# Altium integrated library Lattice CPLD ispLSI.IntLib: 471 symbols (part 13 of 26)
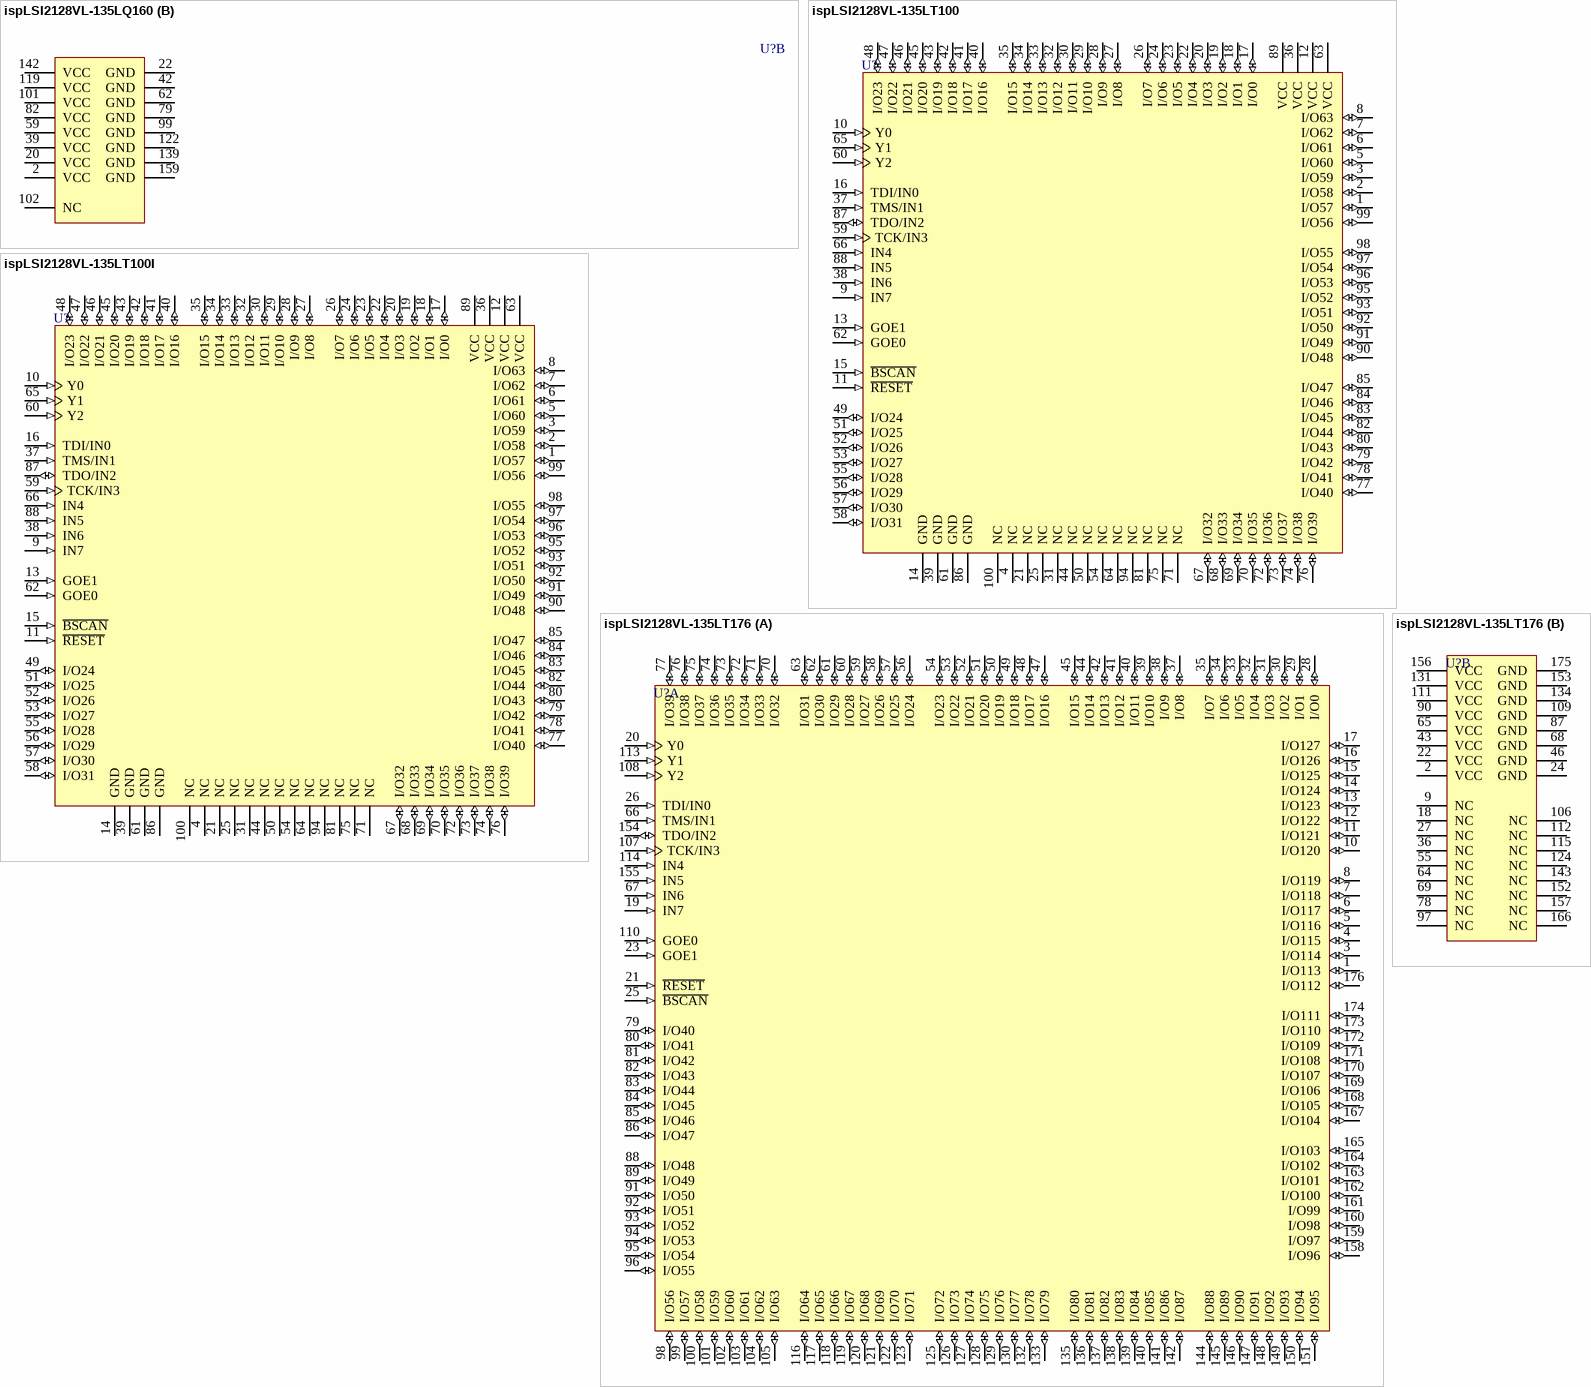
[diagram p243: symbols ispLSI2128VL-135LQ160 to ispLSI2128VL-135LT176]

## ispLSI2128VL-135LT176
designator U?
2.5V In-System Programmable SuperFAST High Density PLD
footprint TQFP176_N (Thin QFP, 176-Leads, Body 24x24mm, Pitch 0.5mm, IPC Medium Density)
footprint TQFP176_L (Thin QFP, 176-Leads, Body 24x24mm, Pitch 0.5mm, IPC High Density)
footprint TQFP176_M (Thin QFP, 176-Leads, Body 24x24mm, Pitch 0.5mm, IPC Low Density)
3D model 2128VL-TQFP176 (176-Pin Thin Quad Flat Pack 0.5 mm Pitch)
part A pins: 1 I/O113 (io), 3 I/O114 (io), 4 I/O115 (io), 5 I/O116 (io), 6 I/O117 (io), 7 I/O118 (io), 8 I/O119 (io), 10 I/O120 (io), 11 I/O121 (io), 12 I/O122 (io), 13 I/O123 (io), 14 I/O124 (io), 15 I/O125 (io), 16 I/O126 (io), 17 I/O127 (io), 19 IN7 (in), 20 Y0 (in), 21 ~{RESET} (in), 23 GOE1 (in), 25 ~{BSCAN} (in), 26 TDI/IN0 (in), 28 I/O0 (io), 29 I/O1 (io), 30 I/O2 (io), 31 I/O3 (io), 32 I/O4 (io), 33 I/O5 (io), 34 I/O6 (io), 35 I/O7 (io), 37 I/O8 (io), 38 I/O9 (io), 39 I/O10 (io), 40 I/O11 (io), 41 I/O12 (io), 42 I/O13 (io), 44 I/O14 (io), 45 I/O15 (io), 47 I/O16 (io), 48 I/O17 (io), 49 I/O18 (io), 50 I/O19 (io), 51 I/O20 (io), 52 I/O21 (io), 53 I/O22 (io), 54 I/O23 (io), 56 I/O24 (io), 57 I/O25 (io), 58 I/O26 (io), 59 I/O27 (io), 60 I/O28 (io), 61 I/O29 (io), 62 I/O30 (io), 63 I/O31 (io), 66 TMS/IN1 (in), 67 IN6 (in), 70 I/O32 (io), 71 I/O33 (io), 72 I/O34 (io), 73 I/O35 (io), 74 I/O36 (io), 75 I/O37 (io), 76 I/O38 (io), 77 I/O39 (io), 79 I/O40 (io), 80 I/O41 (io), 81 I/O42 (io), 82 I/O43 (io), 83 I/O44 (io), 84 I/O45 (io), 85 I/O46 (io), 86 I/O47 (io), 88 I/O48 (io), 89 I/O49 (io), 91 I/O50 (io), 92 I/O51 (io), 93 I/O52 (io), 94 I/O53 (io), 95 I/O54 (io), 96 I/O55 (io), 98 I/O56 (io), 99 I/O57 (io), 100 I/O58 (io), 101 I/O59 (io), 102 I/O60 (io), 103 I/O61 (io), 104 I/O62 (io), 105 I/O63 (io), 107 TCK/IN3 (in), 108 Y2 (in), 110 GOE0 (in), 113 Y1 (in), 114 IN4 (in), 116 I/O64 (io), 117 I/O65 (io), 118 I/O66 (io), 119 I/O67 (io), 120 I/O68 (io), 121 I/O69 (io), 122 I/O70 (io), 123 I/O71 (io), 125 I/O72 (io), 126 I/O73 (io), 127 I/O74 (io), 128 I/O75 (io), 129 I/O76 (io), 130 I/O77 (io), 132 I/O78 (io), 133 I/O79 (io), 135 I/O80 (io), 136 I/O81 (io), 137 I/O82 (io), 138 I/O83 (io), 139 I/O84 (io), 140 I/O85 (io), 141 I/O86 (io), 142 I/O87 (io), 144 I/O88 (io), 145 I/O89 (io), 146 I/O90 (io), 147 I/O91 (io), 148 I/O92 (io), 149 I/O93 (io), 150 I/O94 (io), 151 I/O95 (io), 154 TDO/IN2 (io), 155 IN5 (in), 158 I/O96 (io), 159 I/O97 (io), 160 I/O98 (io), 161 I/O99 (io), 162 I/O100 (io), 163 I/O101 (io), 164 I/O102 (io), 165 I/O103 (io), 167 I/O104 (io), 168 I/O105 (io), 169 I/O106 (io), 170 I/O107 (io), 171 I/O108 (io), 172 I/O109 (io), 173 I/O110 (io), 174 I/O111 (io), 176 I/O112 (io)
part B pins: 2 VCC (power), 9 NC, 18 NC, 22 VCC (power), 24 GND (power), 27 NC, 36 NC, 43 VCC (power), 46 GND (power), 55 NC, 64 NC, 65 VCC (power), 68 GND (power), 69 NC, 78 NC, 87 GND (power), 90 VCC (power), 97 NC, 106 NC, 109 GND (power), 111 VCC (power), 112 NC, 115 NC, 124 NC, 131 VCC (power), 134 GND (power), 143 NC, 152 NC, 153 GND (power), 156 VCC (power), 157 NC, 166 NC, 175 GND (power)

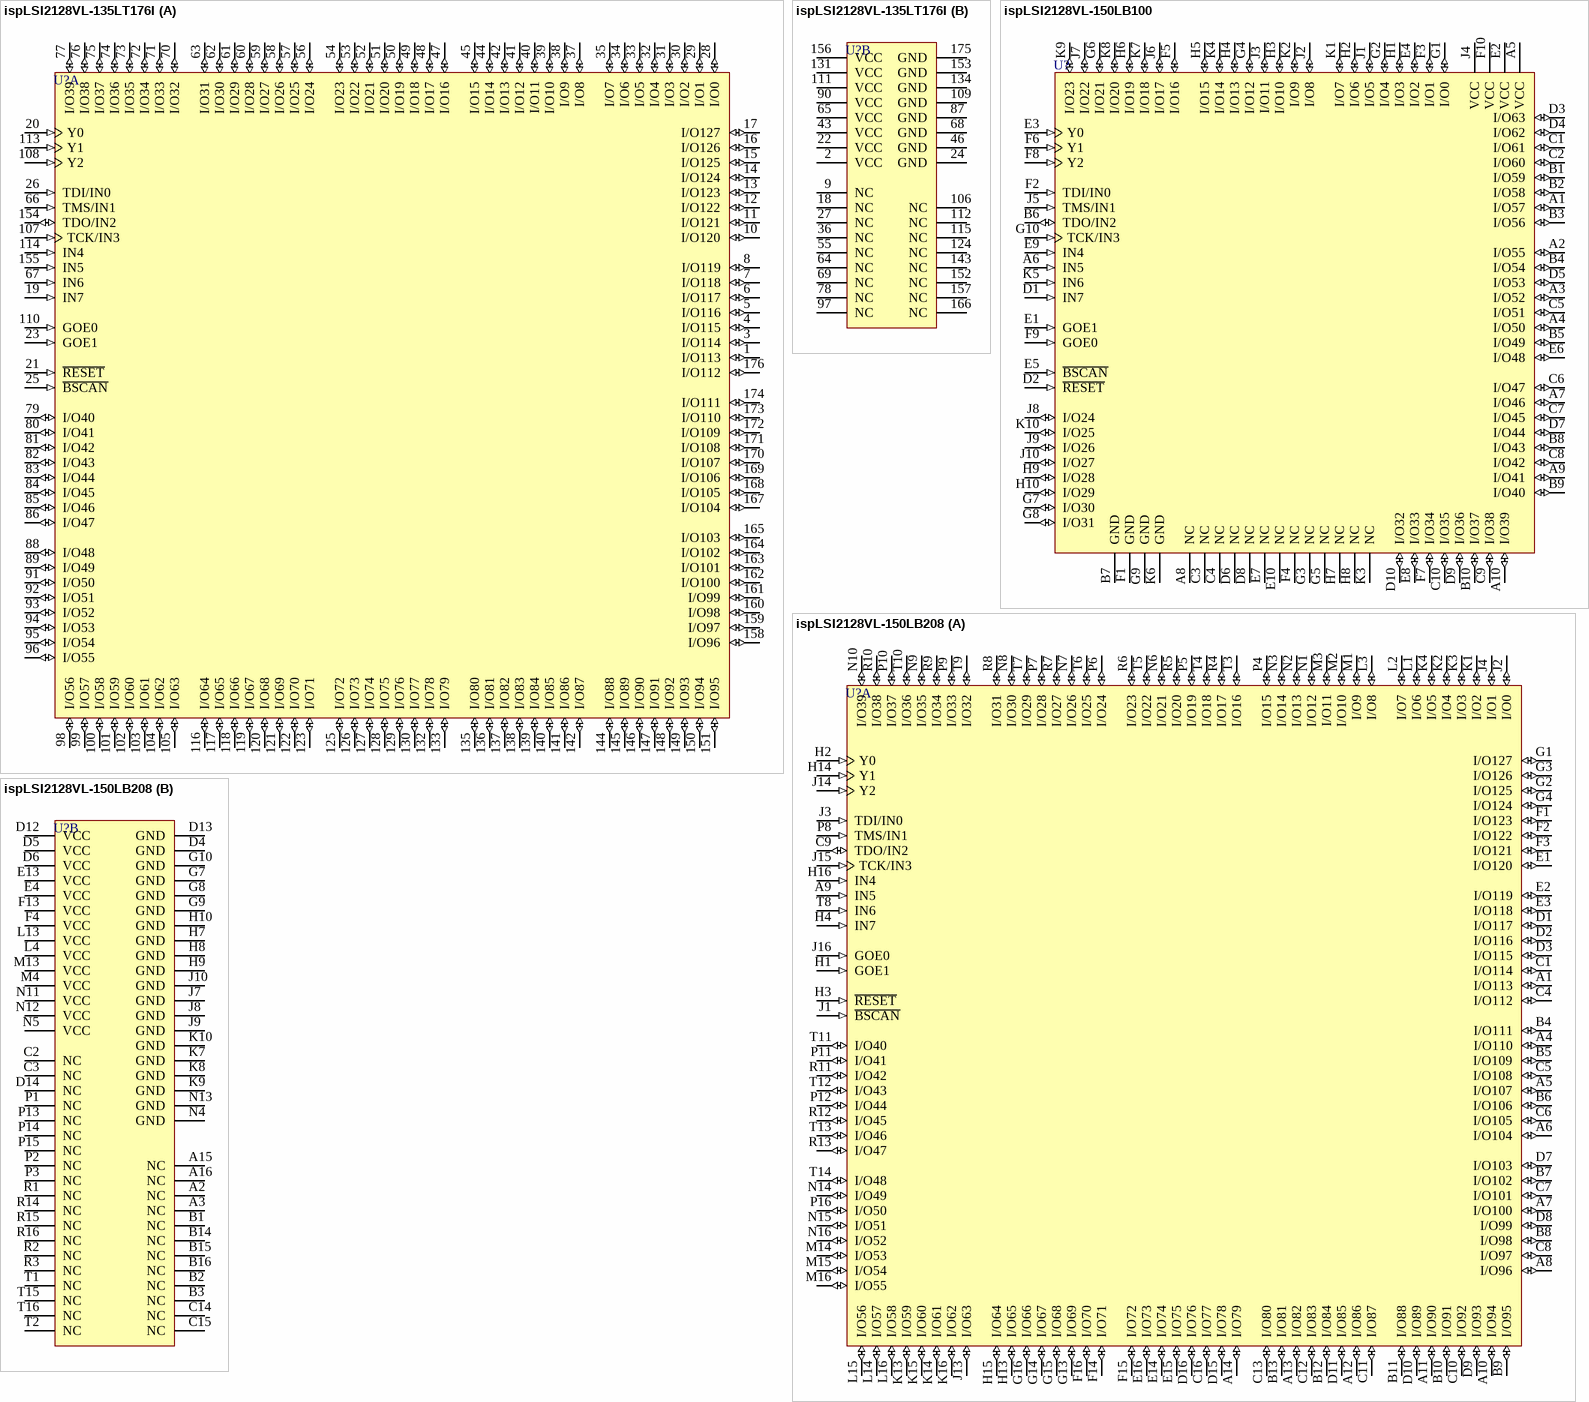
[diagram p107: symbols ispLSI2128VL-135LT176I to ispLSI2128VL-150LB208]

## ispLSI2128VL-135LT176I
designator U?
2.5V In-System Programmable SuperFAST High Density PLD
footprint TQFP176_N (Thin QFP, 176-Leads, Body 24x24mm, Pitch 0.5mm, IPC Medium Density)
footprint TQFP176_L (Thin QFP, 176-Leads, Body 24x24mm, Pitch 0.5mm, IPC High Density)
footprint TQFP176_M (Thin QFP, 176-Leads, Body 24x24mm, Pitch 0.5mm, IPC Low Density)
3D model 2128VL-TQFP176 (176-Pin Thin Quad Flat Pack 0.5 mm Pitch)
part A pins: 1 I/O113 (io), 3 I/O114 (io), 4 I/O115 (io), 5 I/O116 (io), 6 I/O117 (io), 7 I/O118 (io), 8 I/O119 (io), 10 I/O120 (io), 11 I/O121 (io), 12 I/O122 (io), 13 I/O123 (io), 14 I/O124 (io), 15 I/O125 (io), 16 I/O126 (io), 17 I/O127 (io), 19 IN7 (in), 20 Y0 (in), 21 ~{RESET} (in), 23 GOE1 (in), 25 ~{BSCAN} (in), 26 TDI/IN0 (in), 28 I/O0 (io), 29 I/O1 (io), 30 I/O2 (io), 31 I/O3 (io), 32 I/O4 (io), 33 I/O5 (io), 34 I/O6 (io), 35 I/O7 (io), 37 I/O8 (io), 38 I/O9 (io), 39 I/O10 (io), 40 I/O11 (io), 41 I/O12 (io), 42 I/O13 (io), 44 I/O14 (io), 45 I/O15 (io), 47 I/O16 (io), 48 I/O17 (io), 49 I/O18 (io), 50 I/O19 (io), 51 I/O20 (io), 52 I/O21 (io), 53 I/O22 (io), 54 I/O23 (io), 56 I/O24 (io), 57 I/O25 (io), 58 I/O26 (io), 59 I/O27 (io), 60 I/O28 (io), 61 I/O29 (io), 62 I/O30 (io), 63 I/O31 (io), 66 TMS/IN1 (in), 67 IN6 (in), 70 I/O32 (io), 71 I/O33 (io), 72 I/O34 (io), 73 I/O35 (io), 74 I/O36 (io), 75 I/O37 (io), 76 I/O38 (io), 77 I/O39 (io), 79 I/O40 (io), 80 I/O41 (io), 81 I/O42 (io), 82 I/O43 (io), 83 I/O44 (io), 84 I/O45 (io), 85 I/O46 (io), 86 I/O47 (io), 88 I/O48 (io), 89 I/O49 (io), 91 I/O50 (io), 92 I/O51 (io), 93 I/O52 (io), 94 I/O53 (io), 95 I/O54 (io), 96 I/O55 (io), 98 I/O56 (io), 99 I/O57 (io), 100 I/O58 (io), 101 I/O59 (io), 102 I/O60 (io), 103 I/O61 (io), 104 I/O62 (io), 105 I/O63 (io), 107 TCK/IN3 (in), 108 Y2 (in), 110 GOE0 (in), 113 Y1 (in), 114 IN4 (in), 116 I/O64 (io), 117 I/O65 (io), 118 I/O66 (io), 119 I/O67 (io), 120 I/O68 (io), 121 I/O69 (io), 122 I/O70 (io), 123 I/O71 (io), 125 I/O72 (io), 126 I/O73 (io), 127 I/O74 (io), 128 I/O75 (io), 129 I/O76 (io), 130 I/O77 (io), 132 I/O78 (io), 133 I/O79 (io), 135 I/O80 (io), 136 I/O81 (io), 137 I/O82 (io), 138 I/O83 (io), 139 I/O84 (io), 140 I/O85 (io), 141 I/O86 (io), 142 I/O87 (io), 144 I/O88 (io), 145 I/O89 (io), 146 I/O90 (io), 147 I/O91 (io), 148 I/O92 (io), 149 I/O93 (io), 150 I/O94 (io), 151 I/O95 (io), 154 TDO/IN2 (io), 155 IN5 (in), 158 I/O96 (io), 159 I/O97 (io), 160 I/O98 (io), 161 I/O99 (io), 162 I/O100 (io), 163 I/O101 (io), 164 I/O102 (io), 165 I/O103 (io), 167 I/O104 (io), 168 I/O105 (io), 169 I/O106 (io), 170 I/O107 (io), 171 I/O108 (io), 172 I/O109 (io), 173 I/O110 (io), 174 I/O111 (io), 176 I/O112 (io)
part B pins: 2 VCC (power), 9 NC, 18 NC, 22 VCC (power), 24 GND (power), 27 NC, 36 NC, 43 VCC (power), 46 GND (power), 55 NC, 64 NC, 65 VCC (power), 68 GND (power), 69 NC, 78 NC, 87 GND (power), 90 VCC (power), 97 NC, 106 NC, 109 GND (power), 111 VCC (power), 112 NC, 115 NC, 124 NC, 131 VCC (power), 134 GND (power), 143 NC, 152 NC, 153 GND (power), 156 VCC (power), 157 NC, 166 NC, 175 GND (power)

## ispLSI2128VL-150LB100
designator U?
2.5V In-System Programmable SuperFAST High Density PLD
footprint caBGA100 (BGA, 100-Leads, Body 10x10mm, Pitch 0.8mm)
3D model 2128VL-caBGA100 (100-Ball Chip Array Ball Grid Array (caBGA100))
pins: A1 I/O57 (io), A2 I/O55 (io), A3 I/O52 (io), A4 I/O50 (io), A5 VCC (power), A6 IN5 (in), A7 I/O46 (io), A8 NC, A9 I/O41 (io), A10 I/O39 (io), B1 I/O59 (io), B2 I/O58 (io), B3 I/O56 (io), B4 I/O54 (io), B5 I/O49 (io), B6 TDO/IN2 (io), B7 GND (power), B8 I/O43 (io), B9 I/O40 (io), B10 I/O37 (io), C1 I/O61 (io), C2 I/O60 (io), C3 NC, C4 NC, C5 I/O51 (io), C6 I/O47 (io), C7 I/O45 (io), C8 I/O42 (io), C9 I/O38 (io), C10 I/O35 (io), D1 IN7 (in), D2 ~{RESET} (in), D3 I/O63 (io), D4 I/O62 (io), D5 I/O53 (io), D6 NC, D7 I/O44 (io), D8 NC, D9 I/O36 (io), D10 I/O32 (io), E1 GOE1 (in), E2 VCC (power), E3 Y0 (in), E4 I/O2 (io), E5 ~{BSCAN} (in), E6 I/O48 (io), E7 NC, E8 I/O33 (io), E9 IN4 (in), E10 NC, F1 GND (power), F2 TDI/IN0 (in), F3 I/O1 (io), F4 NC, F5 I/O16 (io), F6 Y1 (in), F7 I/O34 (io), F8 Y2 (in), F9 GOE0 (in), F10 VCC (power), G1 I/O0 (io), G2 I/O4 (io), G3 NC, G4 I/O12 (io), G5 NC, G6 I/O21 (io), G7 I/O30 (io), G8 I/O31 (io), G9 GND (power), G10 TCK/IN3 (in), H1 I/O3 (io), H2 I/O6 (io), H3 I/O10 (io), H4 I/O13 (io), H5 I/O15 (io), H6 I/O19 (io), H7 NC, H8 NC, H9 I/O28 (io), H10 I/O29 (io), J1 I/O5 (io), J2 I/O8 (io), J3 I/O11 (io), J4 VCC (power), J5 TMS/IN1 (in), J6 I/O17 (io), J7 I/O22 (io), J8 I/O24 (io), J9 I/O26 (io), J10 I/O27 (io), K1 I/O7 (io), K2 I/O9 (io), K3 NC, K4 I/O14 (io), K5 IN6 (in), K6 GND (power), K7 I/O18 (io), K8 I/O20 (io), K9 I/O23 (io), K10 I/O25 (io)

## ispLSI2128VL-150LB208
designator U?
2.5V In-System Programmable SuperFAST High Density PLD
footprint fpBGA208 (BGA, 208-Leads, Body 17x17mm, Pitch 1mm)
3D model 2128VL-fpBGA208 (208-Ball Fine Pitch Ball Grid Array (fpBGA208))
part A pins: A1 I/O113 (io), A4 I/O110 (io), A5 I/O107 (io), A6 I/O104 (io), A7 I/O100 (io), A8 I/O96 (io), A9 IN5 (in), A10 I/O94 (io), A11 I/O90 (io), A12 I/O86 (io), A13 I/O82 (io), A14 I/O79 (io), B4 I/O111 (io), B5 I/O109 (io), B6 I/O106 (io), B7 I/O102 (io), B8 I/O98 (io), B9 I/O95 (io), B10 I/O91 (io), B11 I/O88 (io), B12 I/O84 (io), B13 I/O81 (io), C1 I/O114 (io), C4 I/O112 (io), C5 I/O108 (io), C6 I/O105 (io), C7 I/O101 (io), C8 I/O97 (io), C9 TDO/IN2 (io), C10 I/O92 (io), C11 I/O87 (io), C12 I/O83 (io), C13 I/O80 (io), C16 I/O77 (io), D1 I/O117 (io), D2 I/O116 (io), D3 I/O115 (io), D7 I/O103 (io), D8 I/O99 (io), D9 I/O93 (io), D10 I/O89 (io), D11 I/O85 (io), D15 I/O78 (io), D16 I/O76 (io), E1 I/O120 (io), E2 I/O119 (io), E3 I/O118 (io), E14 I/O74 (io), E15 I/O75 (io), E16 I/O73 (io), F1 I/O123 (io), F2 I/O122 (io), F3 I/O121 (io), F14 I/O71 (io), F15 I/O72 (io), F16 I/O70 (io), G1 I/O127 (io), G2 I/O125 (io), G3 I/O126 (io), G4 I/O124 (io), G13 I/O69 (io), G14 I/O67 (io), G15 I/O68 (io), G16 I/O66 (io), H1 GOE1 (in), H2 Y0 (in), H3 ~{RESET} (in), H4 IN7 (in), H13 I/O65 (io), H14 Y1 (in), H15 I/O64 (io), H16 IN4 (in), J1 ~{BSCAN} (in), J2 I/O0 (io), J3 TDI/IN0 (in), J4 I/O1 (io), J13 I/O63 (io), J14 Y2 (in), J15 TCK/IN3 (in), J16 GOE0 (in), K1 I/O2 (io), K2 I/O4 (io), K3 I/O3 (io), K4 I/O5 (io), K13 I/O59 (io), K14 I/O61 (io), K15 I/O60 (io), K16 I/O62 (io), L1 I/O6 (io), L2 I/O7 (io), L3 I/O8 (io), L14 I/O57 (io), L15 I/O56 (io), L16 I/O58 (io), M1 I/O9 (io), M2 I/O10 (io), M3 I/O11 (io), M14 I/O53 (io), M15 I/O54 (io), M16 I/O55 (io), N1 I/O12 (io), N2 I/O13 (io), N3 I/O14 (io), N6 I/O21 (io), N7 I/O26 (io), N8 I/O30 (io), N9 I/O35 (io), N10 I/O39 (io), N14 I/O49 (io), N15 I/O51 (io), N16 I/O52 (io), P4 I/O15 (io), P5 I/O19 (io), P6 I/O24 (io), P7 I/O28 (io), P8 TMS/IN1 (in), P9 I/O33 (io), P10 I/O37 (io), P11 I/O41 (io), P12 I/O44 (io), P16 I/O50 (io), R4 I/O17 (io), R5 I/O20 (io), R6 I/O23 (io), R7 I/O27 (io), R8 I/O31 (io), R9 I/O34 (io), R10 I/O38 (io), R11 I/O42 (io), R12 I/O45 (io), R13 I/O47 (io), T3 I/O16 (io), T4 I/O18 (io), T5 I/O22 (io), T6 I/O25 (io), T7 I/O29 (io), T8 IN6 (in), T9 I/O32 (io), T10 I/O36 (io), T11 I/O40 (io), T12 I/O43 (io), T13 I/O46 (io), T14 I/O48 (io)
part B pins: A2 NC, A3 NC, A15 NC, A16 NC, B1 NC, B2 NC, B3 NC, B14 NC, B15 NC, B16 NC, C2 NC, C3 NC, C14 NC, C15 NC, D4 GND (power), D5 VCC (power), D6 VCC (power), D12 VCC (power), D13 GND (power), D14 NC, E4 VCC (power), E13 VCC (power), F4 VCC (power), F13 VCC (power), G7 GND (power), G8 GND (power), G9 GND (power), G10 GND (power), H7 GND (power), H8 GND (power), H9 GND (power), H10 GND (power), J7 GND (power), J8 GND (power), J9 GND (power), J10 GND (power), K7 GND (power), K8 GND (power), K9 GND (power), K10 GND (power), L4 VCC (power), L13 VCC (power), M4 VCC (power), M13 VCC (power), N4 GND (power), N5 VCC (power), N11 VCC (power), N12 VCC (power), N13 GND (power), P1 NC, P2 NC, P3 NC, P13 NC, P14 NC, P15 NC, R1 NC, R2 NC, R3 NC, R14 NC, R15 NC, R16 NC, T1 NC, T2 NC, T15 NC, T16 NC

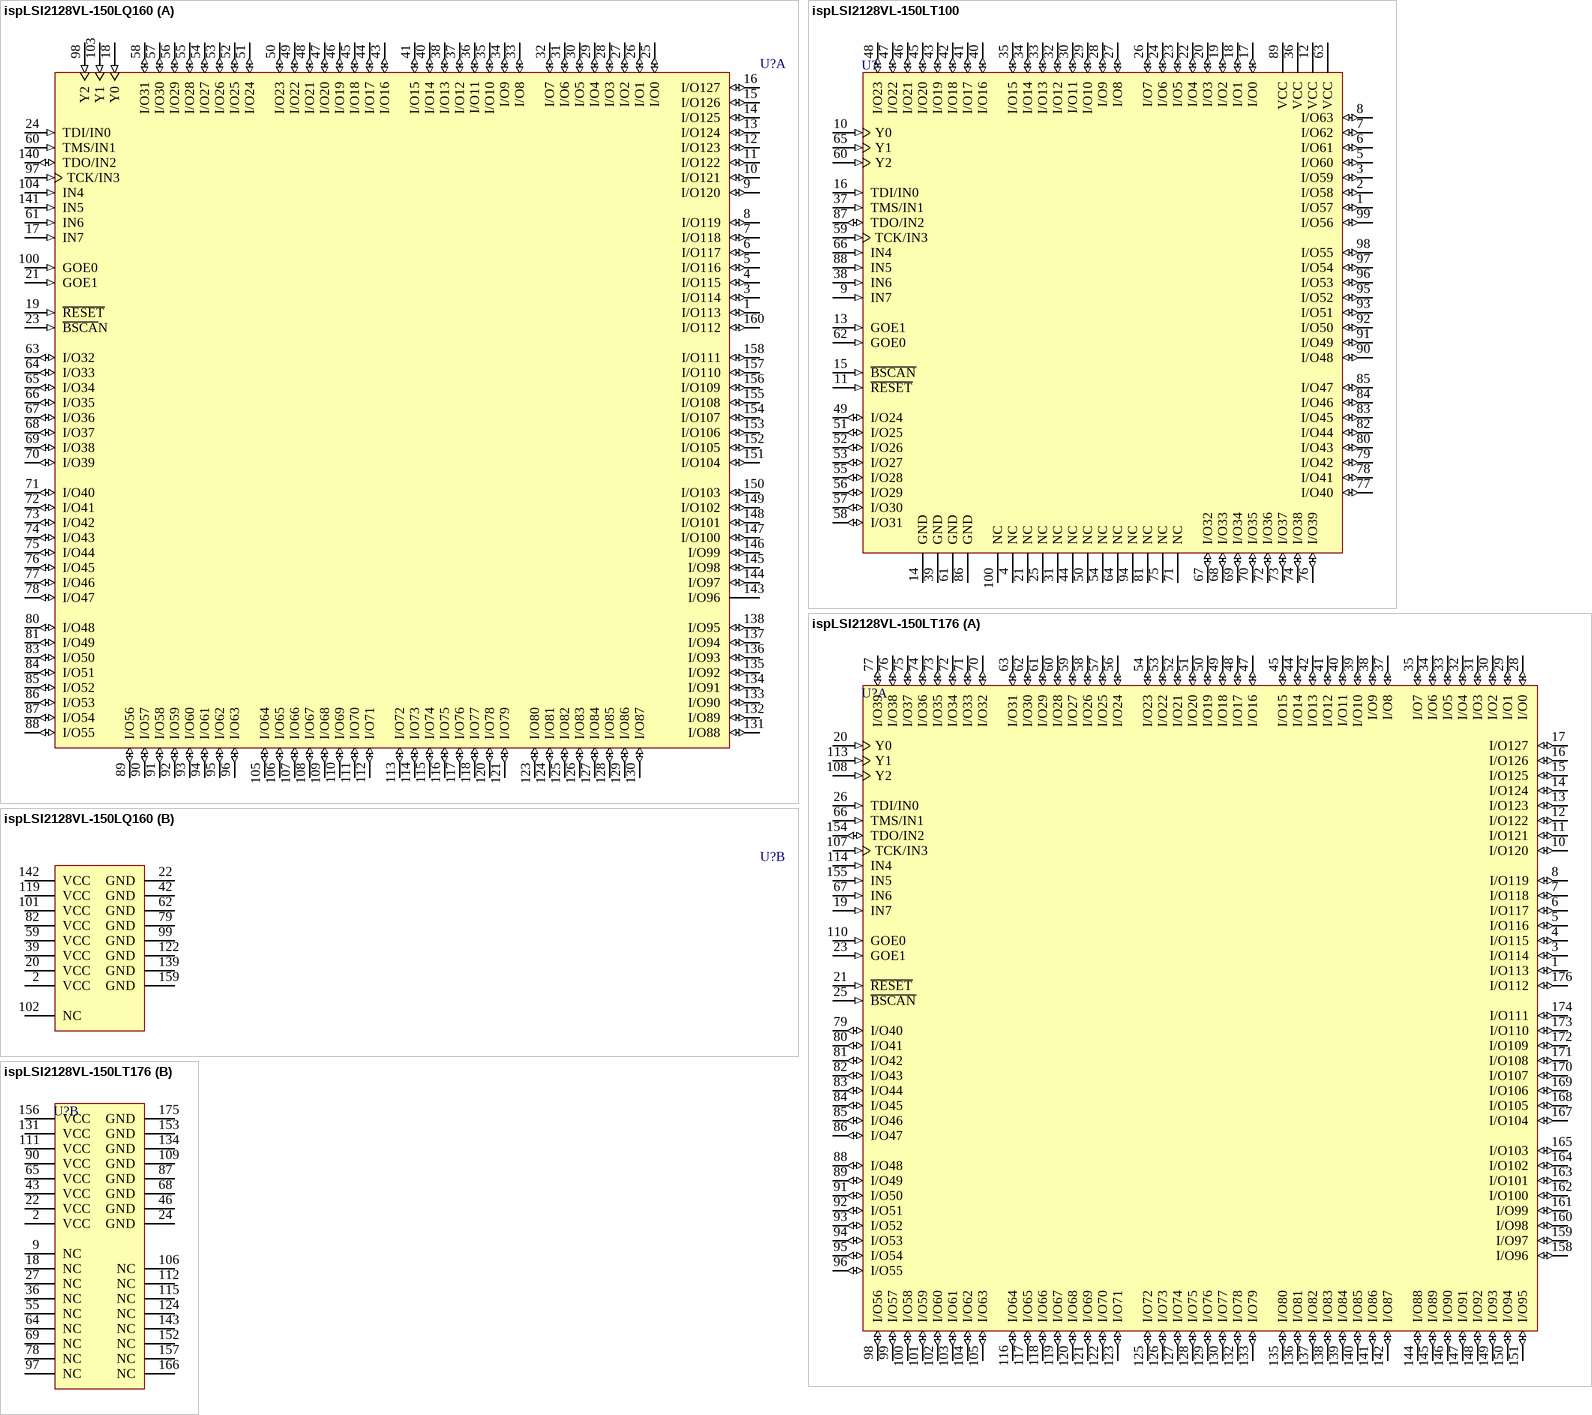
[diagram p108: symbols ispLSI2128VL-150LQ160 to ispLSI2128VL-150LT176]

## ispLSI2128VL-150LQ160
designator U?
2.5V In-System Programmable SuperFAST High Density PLD
footprint PQFP160_N (QFP, 160-Leads, Body 28 x 28mm, Pitch 0.65mm, IPC Medium Density)
footprint PQFP160_L (QFP, 160-Leads, Body 28 x 28mm, Pitch 0.65mm, IPC High Density)
footprint PQFP160_M (QFP, 160-Leads, Body 28 x 28mm, Pitch 0.65mm, IPC Low Density)
3D model 2128VL-PQFP160 (160-Pin Quad Flat Pack 0.65 mm Pitch)
part A pins: 1 I/O113 (io), 3 I/O114 (io), 4 I/O115 (io), 5 I/O116 (io), 6 I/O117 (io), 7 I/O118 (io), 8 I/O119 (io), 9 I/O120 (io), 10 I/O121 (io), 11 I/O122 (io), 12 I/O123 (io), 13 I/O124 (io), 14 I/O125 (io), 15 I/O126 (io), 16 I/O127 (io), 17 IN7 (in), 18 Y0 (in), 19 ~{RESET} (in), 21 GOE1 (in), 23 ~{BSCA}N (in), 24 TDI/IN0 (in), 25 I/O0 (io), 26 I/O1 (io), 27 I/O2 (io), 28 I/O3 (io), 29 I/O4 (io), 30 I/O5 (io), 31 I/O6 (io), 32 I/O7 (io), 33 I/O8 (io), 34 I/O9 (io), 35 I/O10 (io), 36 I/O11 (io), 37 I/O12 (io), 38 I/O13 (io), 40 I/O14 (io), 41 I/O15 (io), 43 I/O16 (io), 44 I/O17 (io), 45 I/O18 (io), 46 I/O19 (io), 47 I/O20 (io), 48 I/O21 (io), 49 I/O22 (io), 50 I/O23 (io), 51 I/O24 (io), 52 I/O25 (io), 53 I/O26 (io), 54 I/O27 (io), 55 I/O28 (io), 56 I/O29 (io), 57 I/O30 (io), 58 I/O31 (io), 60 TMS/IN1 (in), 61 IN6 (in), 63 I/O32 (io), 64 I/O33 (io), 65 I/O34 (io), 66 I/O35 (io), 67 I/O36 (io), 68 I/O37 (io), 69 I/O38 (io), 70 I/O39 (io), 71 I/O40 (io), 72 I/O41 (io), 73 I/O42 (io), 74 I/O43 (io), 75 I/O44 (io), 76 I/O45 (io), 77 I/O46 (io), 78 I/O47 (io), 80 I/O48 (io), 81 I/O49 (io), 83 I/O50 (io), 84 I/O51 (io), 85 I/O52 (io), 86 I/O53 (io), 87 I/O54 (io), 88 I/O55 (io), 89 I/O56 (io), 90 I/O57 (io), 91 I/O58 (io), 92 I/O59 (io), 93 I/O60 (io), 94 I/O61 (io), 95 I/O62 (io), 96 I/O63 (io), 97 TCK/IN3 (in), 98 Y2 (in), 100 GOE0 (in), 103 Y1 (in), 104 IN4 (in), 105 I/O64 (io), 106 I/O65 (io), 107 I/O66 (io), 108 I/O67 (io), 109 I/O68 (io), 110 I/O69 (io), 111 I/O70 (io), 112 I/O71 (io), 113 I/O72 (io), 114 I/O73 (io), 115 I/O74 (io), 116 I/O75 (io), 117 I/O76 (io), 118 I/O77 (io), 120 I/O78 (io), 121 I/O79 (io), 123 I/O80 (io), 124 I/O81 (io), 125 I/O82 (io), 126 I/O83 (io), 127 I/O84 (io), 128 I/O85 (io), 129 I/O86 (io), 130 I/O87 (io), 131 I/O88 (io), 132 I/O89 (io), 133 I/O90 (io), 134 I/O91 (io), 135 I/O92 (io), 136 I/O93 (io), 137 I/O94 (io), 138 I/O95 (io), 140 TDO/IN2 (io), 141 IN5 (in), 143 I/O96 (power), 144 I/O97 (io), 145 I/O98 (io), 146 I/O99 (io), 147 I/O100 (io), 148 I/O101 (io), 149 I/O102 (io), 150 I/O103 (io), 151 I/O104 (io), 152 I/O105 (io), 153 I/O106 (io), 154 I/O107 (io), 155 I/O108 (io), 156 I/O109 (io), 157 I/O110 (io), 158 I/O111 (io), 160 I/O112 (io)
part B pins: 2 VCC (power), 20 VCC (power), 22 GND (power), 39 VCC (power), 42 GND (power), 59 VCC (power), 62 GND (power), 79 GND (power), 82 VCC (power), 99 GND (power), 101 VCC (power), 102 NC, 119 VCC (power), 122 GND (power), 139 GND (power), 142 VCC (power), 159 GND (power)

## ispLSI2128VL-150LT100
designator U?
2.5V In-System Programmable SuperFAST High Density PLD
footprint TQFP100_N (Thin QFP, 100-Leads, Body 14x14mm, Pitch 0.5mm, IPC Medium Density)
footprint TQFP100_L (Thin QFP, 100-Leads, Body 14x14mm, Pitch 0.5mm, IPC High Density)
footprint TQFP100_M (Thin QFP, 100-Leads, Body 14x14mm, Pitch 0.5mm, IPC Low Density)
3D model 2128VL-TQFP100 (100-Pin Thin Quad Flat Pack (TQFP100))
pins: 1 I/O57 (io), 2 I/O58 (io), 3 I/O59 (io), 4 NC, 5 I/O60 (io), 6 I/O61 (io), 7 I/O62 (io), 8 I/O63 (io), 9 IN7 (in), 10 Y0 (in), 11 ~{RESET} (in), 12 VCC (power), 13 GOE1 (in), 14 GND (power), 15 ~{BSCAN} (in), 16 TDI/IN0 (in), 17 I/O0 (io), 18 I/O1 (io), 19 I/O2 (io), 20 I/O3 (io), 21 NC, 22 I/O4 (io), 23 I/O5 (io), 24 I/O6 (io), 25 NC, 26 I/O7 (io), 27 I/O8 (io), 28 I/O9 (io), 29 I/O10 (io), 30 I/O11 (io), 31 NC, 32 I/O12 (io), 33 I/O13 (io), 34 I/O14 (io), 35 I/O15 (io), 36 VCC (power), 37 TMS/IN1 (in), 38 IN6 (in), 39 GND (power), 40 I/O16 (io), 41 I/O17 (io), 42 I/O18 (io), 43 I/O19 (io), 44 NC, 45 I/O20 (io), 46 I/O21 (io), 47 I/O22 (io), 48 I/O23 (io), 49 I/O24 (io), 50 NC, 51 I/O25 (io), 52 I/O26 (io), 53 I/O27 (io), 54 NC, 55 I/O28 (io), 56 I/O29 (io), 57 I/O30 (io), 58 I/O31 (io), 59 TCK/IN3 (in), 60 Y2 (in), 61 GND (power), 62 GOE0 (in), 63 VCC (power), 64 NC, 65 Y1 (in), 66 IN4 (in), 67 I/O32 (io), 68 I/O33 (io), 69 I/O34 (io), 70 I/O35 (io), 71 NC, 72 I/O36 (io), 73 I/O37 (io), 74 I/O38 (io), 75 NC, 76 I/O39 (io), 77 I/O40 (io), 78 I/O41 (io), 79 I/O42 (io), 80 I/O43 (io), 81 NC, 82 I/O44 (io), 83 I/O45 (io), 84 I/O46 (io), 85 I/O47 (io), 86 GND (power), 87 TDO/IN2 (io), 88 IN5 (in), 89 VCC (power), 90 I/O48 (io), 91 I/O49 (io), 92 I/O50 (io), 93 I/O51 (io), 94 NC, 95 I/O52 (io), 96 I/O53 (io), 97 I/O54 (io), 98 I/O55 (io), 99 I/O56 (io), 100 NC

## ispLSI2128VL-150LT176
designator U?
2.5V In-System Programmable SuperFAST High Density PLD
footprint TQFP176_N (Thin QFP, 176-Leads, Body 24x24mm, Pitch 0.5mm, IPC Medium Density)
footprint TQFP176_L (Thin QFP, 176-Leads, Body 24x24mm, Pitch 0.5mm, IPC High Density)
footprint TQFP176_M (Thin QFP, 176-Leads, Body 24x24mm, Pitch 0.5mm, IPC Low Density)
3D model 2128VL-TQFP176 (176-Pin Thin Quad Flat Pack 0.5 mm Pitch)
part A pins: 1 I/O113 (io), 3 I/O114 (io), 4 I/O115 (io), 5 I/O116 (io), 6 I/O117 (io), 7 I/O118 (io), 8 I/O119 (io), 10 I/O120 (io), 11 I/O121 (io), 12 I/O122 (io), 13 I/O123 (io), 14 I/O124 (io), 15 I/O125 (io), 16 I/O126 (io), 17 I/O127 (io), 19 IN7 (in), 20 Y0 (in), 21 ~{RESET} (in), 23 GOE1 (in), 25 ~{BSCAN} (in), 26 TDI/IN0 (in), 28 I/O0 (io), 29 I/O1 (io), 30 I/O2 (io), 31 I/O3 (io), 32 I/O4 (io), 33 I/O5 (io), 34 I/O6 (io), 35 I/O7 (io), 37 I/O8 (io), 38 I/O9 (io), 39 I/O10 (io), 40 I/O11 (io), 41 I/O12 (io), 42 I/O13 (io), 44 I/O14 (io), 45 I/O15 (io), 47 I/O16 (io), 48 I/O17 (io), 49 I/O18 (io), 50 I/O19 (io), 51 I/O20 (io), 52 I/O21 (io), 53 I/O22 (io), 54 I/O23 (io), 56 I/O24 (io), 57 I/O25 (io), 58 I/O26 (io), 59 I/O27 (io), 60 I/O28 (io), 61 I/O29 (io), 62 I/O30 (io), 63 I/O31 (io), 66 TMS/IN1 (in), 67 IN6 (in), 70 I/O32 (io), 71 I/O33 (io), 72 I/O34 (io), 73 I/O35 (io), 74 I/O36 (io), 75 I/O37 (io), 76 I/O38 (io), 77 I/O39 (io), 79 I/O40 (io), 80 I/O41 (io), 81 I/O42 (io), 82 I/O43 (io), 83 I/O44 (io), 84 I/O45 (io), 85 I/O46 (io), 86 I/O47 (io), 88 I/O48 (io), 89 I/O49 (io), 91 I/O50 (io), 92 I/O51 (io), 93 I/O52 (io), 94 I/O53 (io), 95 I/O54 (io), 96 I/O55 (io), 98 I/O56 (io), 99 I/O57 (io), 100 I/O58 (io), 101 I/O59 (io), 102 I/O60 (io), 103 I/O61 (io), 104 I/O62 (io), 105 I/O63 (io), 107 TCK/IN3 (in), 108 Y2 (in), 110 GOE0 (in), 113 Y1 (in), 114 IN4 (in), 116 I/O64 (io), 117 I/O65 (io), 118 I/O66 (io), 119 I/O67 (io), 120 I/O68 (io), 121 I/O69 (io), 122 I/O70 (io), 123 I/O71 (io), 125 I/O72 (io), 126 I/O73 (io), 127 I/O74 (io), 128 I/O75 (io), 129 I/O76 (io), 130 I/O77 (io), 132 I/O78 (io), 133 I/O79 (io), 135 I/O80 (io), 136 I/O81 (io), 137 I/O82 (io), 138 I/O83 (io), 139 I/O84 (io), 140 I/O85 (io), 141 I/O86 (io), 142 I/O87 (io), 144 I/O88 (io), 145 I/O89 (io), 146 I/O90 (io), 147 I/O91 (io), 148 I/O92 (io), 149 I/O93 (io), 150 I/O94 (io), 151 I/O95 (io), 154 TDO/IN2 (io), 155 IN5 (in), 158 I/O96 (io), 159 I/O97 (io), 160 I/O98 (io), 161 I/O99 (io), 162 I/O100 (io), 163 I/O101 (io), 164 I/O102 (io), 165 I/O103 (io), 167 I/O104 (io), 168 I/O105 (io), 169 I/O106 (io), 170 I/O107 (io), 171 I/O108 (io), 172 I/O109 (io), 173 I/O110 (io), 174 I/O111 (io), 176 I/O112 (io)
part B pins: 2 VCC (power), 9 NC, 18 NC, 22 VCC (power), 24 GND (power), 27 NC, 36 NC, 43 VCC (power), 46 GND (power), 55 NC, 64 NC, 65 VCC (power), 68 GND (power), 69 NC, 78 NC, 87 GND (power), 90 VCC (power), 97 NC, 106 NC, 109 GND (power), 111 VCC (power), 112 NC, 115 NC, 124 NC, 131 VCC (power), 134 GND (power), 143 NC, 152 NC, 153 GND (power), 156 VCC (power), 157 NC, 166 NC, 175 GND (power)

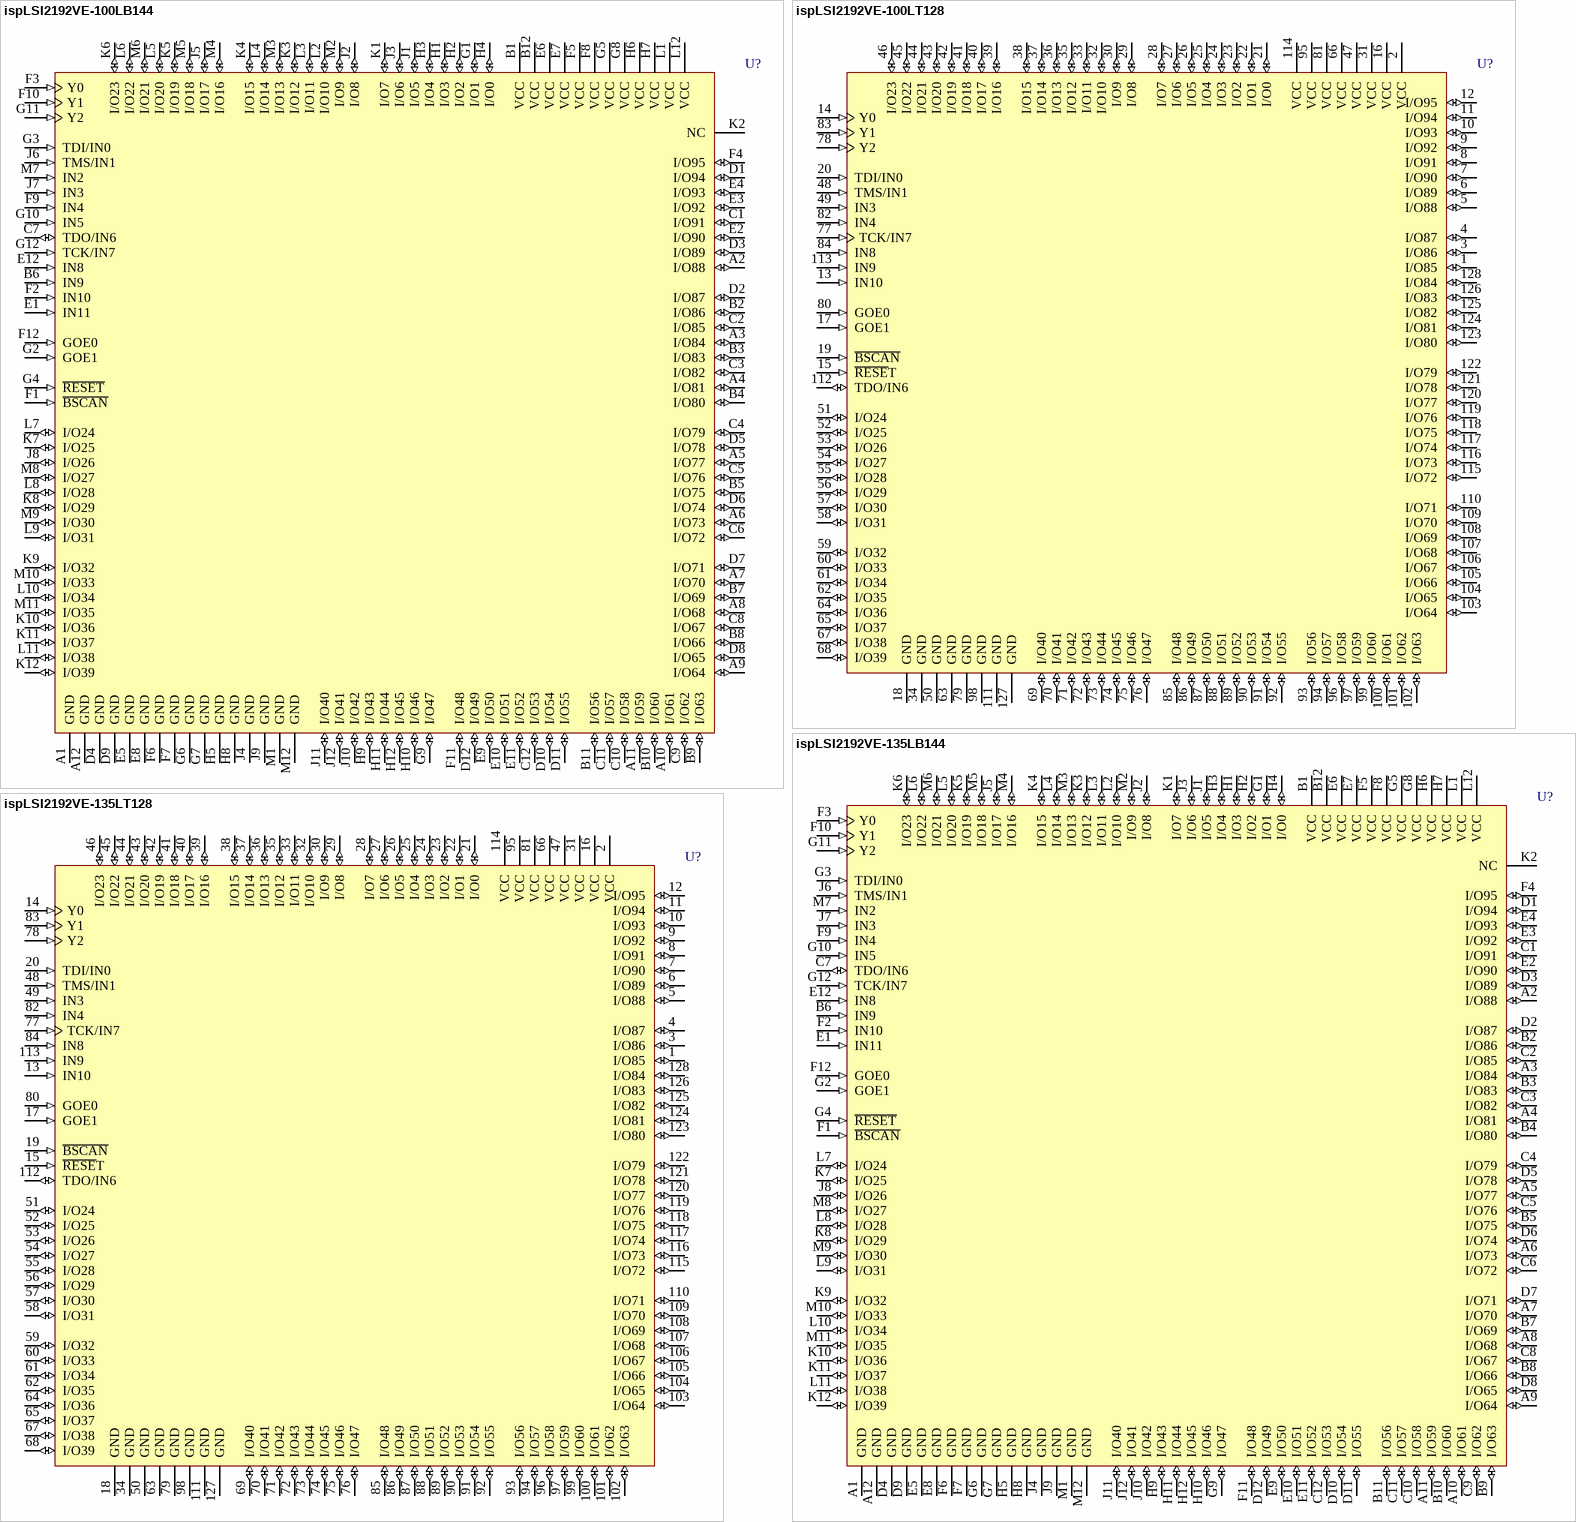
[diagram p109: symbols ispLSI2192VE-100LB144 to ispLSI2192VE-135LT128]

## ispLSI2192VE-100LB144
designator U?
3.3V In-System Programmable SuperFAST High Density PLD
footprint fpBGA144 (BGA, 144-Leads, Body 13x13mm, Pitch 1mm)
3D model 2192VE-fpBGA144 (144-Ball Fine Pitch Ball Grid Array (fpBGA144))
pins: A1 GND (power), A2 I/O88 (io), A3 I/O84 (io), A4 I/O81 (io), A5 I/O77 (io), A6 I/O73 (io), A7 I/O70 (io), A8 I/O68 (io), A9 I/O64 (io), A10 I/O61 (io), A11 I/O59 (io), A12 GND (power), B1 VCC (power), B2 I/O86 (io), B3 I/O83 (io), B4 I/O80 (io), B5 I/O75 (io), B6 IN9 (in), B7 I/O69 (io), B8 I/O66 (io), B9 I/O63 (io), B10 I/O60 (io), B11 I/O56 (io), B12 VCC (power), C1 I/O91 (io), C2 I/O85 (io), C3 I/O82 (io), C4 I/O79 (io), C5 I/O76 (io), C6 I/O72 (io), C7 TDO/IN6 (io), C8 I/O67 (io), C9 I/O62 (io), C10 I/O58 (io), C11 I/O57 (io), C12 I/O53 (io), D1 I/O94 (io), D2 I/O87 (io), D3 I/O89 (io), D4 GND (power), D5 I/O78 (io), D6 I/O74 (io), D7 I/O71 (io), D8 I/O65 (io), D9 GND (power), D10 I/O54 (io), D11 I/O55 (io), D12 I/O49 (io), E1 IN11 (in), E2 I/O90 (io), E3 I/O92 (io), E4 I/O93 (io), E5 GND (power), E6 VCC (power), E7 VCC (power), E8 GND (power), E9 I/O50 (io), E10 I/O51 (io), E11 I/O52 (io), E12 IN8 (in), F1 ~{BSCAN} (in), F2 IN10 (in), F3 Y0 (in), F4 I/O95 (io), F5 VCC (power), F6 GND (power), F7 GND (power), F8 VCC (power), F9 IN4 (in), F10 Y1 (in), F11 I/O48 (io), F12 GOE0 (in), G1 I/O1 (io), G2 GOE1 (in), G3 TDI/IN0 (in), G4 ~{RESET} (in), G5 VCC (power), G6 GND (power), G7 GND (power), G8 VCC (power), G9 I/O47 (io), G10 IN5 (in), G11 Y2 (in), G12 TCK/IN7 (in), H1 I/O3 (io), H2 I/O2 (io), H3 I/O4 (io), H4 I/O0 (io), H5 GND (power), H6 VCC (power), H7 VCC (power), H8 GND (power), H9 I/O43 (io), H10 I/O46 (io), H11 I/O44 (io), H12 I/O45 (io), J1 I/O5 (io), J2 I/O8 (io), J3 I/O6 (io), J4 GND (power), J5 I/O17 (io), J6 TMS/IN1 (in), J7 IN3 (in), J8 I/O26 (io), J9 GND (power), J10 I/O42 (io), J11 I/O40 (io), J12 I/O41 (io), K1 I/O7 (io), K2 NC, K3 I/O12 (io), K4 I/O15 (io), K5 I/O19 (io), K6 I/O23 (io), K7 I/O25 (io), K8 I/O29 (io), K9 I/O32 (io), K10 I/O36 (io), K11 I/O37 (io), K12 I/O39 (io), L1 VCC (power), L2 I/O10 (io), L3 I/O11 (io), L4 I/O14 (io), L5 I/O20 (io), L6 I/O22 (io), L7 I/O24 (io), L8 I/O28 (io), L9 I/O31 (io), L10 I/O34 (io), L11 I/O38 (io), L12 VCC (power), M1 GND (power), M2 I/O9 (io), M3 I/O13 (io), M4 I/O16 (io), M5 I/O18 (io), M6 I/O21 (io), M7 IN2 (in), M8 I/O27 (io), M9 I/O30 (io), M10 I/O33 (io), M11 I/O35 (io), M12 GND (power)

## ispLSI2192VE-100LT128
designator U?
3.3V In-System Programmable SuperFAST High Density PLD
footprint TQFP128_N (Thin QFP, 128-Leads, Body 14x14mm, Pitch 0.4mm, IPC Medium Density)
footprint TQFP128_L (Thin QFP, 128-Leads, Body 14x14mm, Pitch 0.4mm, IPC High Density)
footprint TQFP128_M (Thin QFP, 128-Leads, Body 14x14mm, Pitch 0.4mm, IPC Low Density)
3D model 2192VE-TQFP128 (128-Pin Thin Quad Flat Pack 0.4 mm Pitch)
pins: 1 I/O85 (io), 2 VCC (power), 3 I/O86 (io), 4 I/O87 (io), 5 I/O88 (io), 6 I/O89 (io), 7 I/O90 (io), 8 I/O91 (io), 9 I/O92 (io), 10 I/O93 (io), 11 I/O94 (io), 12 I/O95 (io), 13 IN10 (in), 14 Y0 (in), 15 ~{RESE}T (in), 16 VCC (power), 17 GOE1 (in), 18 GND (power), 19 ~{BSCAN} (in), 20 TDI/IN0 (in), 21 I/O0 (io), 22 I/O1 (io), 23 I/O2 (io), 24 I/O3 (io), 25 I/O4 (io), 26 I/O5 (io), 27 I/O6 (io), 28 I/O7 (io), 29 I/O8 (io), 30 I/O9 (io), 31 VCC (power), 32 I/O10 (io), 33 I/O11 (io), 34 GND (power), 35 I/O12 (io), 36 I/O13 (io), 37 I/O14 (io), 38 I/O15 (io), 39 I/O16 (io), 40 I/O17 (io), 41 I/O18 (io), 42 I/O19 (io), 43 I/O20 (io), 44 I/O21 (io), 45 I/O22 (io), 46 I/O23 (io), 47 VCC (power), 48 TMS/IN1 (in), 49 IN3 (in), 50 GND (power), 51 I/O24 (io), 52 I/O25 (io), 53 I/O26 (io), 54 I/O27 (io), 55 I/O28 (io), 56 I/O29 (io), 57 I/O30 (io), 58 I/O31 (io), 59 I/O32 (io), 60 I/O33 (io), 61 I/O34 (io), 62 I/O35 (io), 63 GND (power), 64 I/O36 (io), 65 I/O37 (io), 66 VCC (power), 67 I/O38 (io), 68 I/O39 (io), 69 I/O40 (io), 70 I/O41 (io), 71 I/O42 (io), 72 I/O43 (io), 73 I/O44 (io), 74 I/O45 (io), 75 I/O46 (io), 76 I/O47 (io), 77 TCK/IN7 (in), 78 Y2 (in), 79 GND (power), 80 GOE0 (in), 81 VCC (power), 82 IN4 (in), 83 Y1 (in), 84 IN8 (in), 85 I/O48 (io), 86 I/O49 (io), 87 I/O50 (io), 88 I/O51 (io), 89 I/O52 (io), 90 I/O53 (io), 91 I/O54 (io), 92 I/O55 (io), 93 I/O56 (io), 94 I/O57 (io), 95 VCC (power), 96 I/O58 (io), 97 I/O59 (io), 98 GND (power), 99 I/O60 (io), 100 I/O61 (io), 101 I/O62 (io), 102 I/O63 (io), 103 I/O64 (io), 104 I/O65 (io), 105 I/O66 (io), 106 I/O67 (io), 107 I/O68 (io), 108 I/O69 (io), 109 I/O70 (io), 110 I/O71 (io), 111 GND (power), 112 TDO/IN6 (io), 113 IN9 (in), 114 VCC (power), 115 I/O72 (io), 116 I/O73 (io), 117 I/O74 (io), 118 I/O75 (io), 119 I/O76 (io), 120 I/O77 (io), 121 I/O78 (io), 122 I/O79 (io), 123 I/O80 (io), 124 I/O81 (io), 125 I/O82 (io), 126 I/O83 (io), 127 GND (power), 128 I/O84 (io)

## ispLSI2192VE-135LB144
designator U?
3.3V In-System Programmable SuperFAST High Density PLD
footprint fpBGA144 (BGA, 144-Leads, Body 13x13mm, Pitch 1mm)
3D model 2192VE-fpBGA144 (144-Ball Fine Pitch Ball Grid Array (fpBGA144))
pins: A1 GND (power), A2 I/O88 (io), A3 I/O84 (io), A4 I/O81 (io), A5 I/O77 (io), A6 I/O73 (io), A7 I/O70 (io), A8 I/O68 (io), A9 I/O64 (io), A10 I/O61 (io), A11 I/O59 (io), A12 GND (power), B1 VCC (power), B2 I/O86 (io), B3 I/O83 (io), B4 I/O80 (io), B5 I/O75 (io), B6 IN9 (in), B7 I/O69 (io), B8 I/O66 (io), B9 I/O63 (io), B10 I/O60 (io), B11 I/O56 (io), B12 VCC (power), C1 I/O91 (io), C2 I/O85 (io), C3 I/O82 (io), C4 I/O79 (io), C5 I/O76 (io), C6 I/O72 (io), C7 TDO/IN6 (io), C8 I/O67 (io), C9 I/O62 (io), C10 I/O58 (io), C11 I/O57 (io), C12 I/O53 (io), D1 I/O94 (io), D2 I/O87 (io), D3 I/O89 (io), D4 GND (power), D5 I/O78 (io), D6 I/O74 (io), D7 I/O71 (io), D8 I/O65 (io), D9 GND (power), D10 I/O54 (io), D11 I/O55 (io), D12 I/O49 (io), E1 IN11 (in), E2 I/O90 (io), E3 I/O92 (io), E4 I/O93 (io), E5 GND (power), E6 VCC (power), E7 VCC (power), E8 GND (power), E9 I/O50 (io), E10 I/O51 (io), E11 I/O52 (io), E12 IN8 (in), F1 ~{BSCAN} (in), F2 IN10 (in), F3 Y0 (in), F4 I/O95 (io), F5 VCC (power), F6 GND (power), F7 GND (power), F8 VCC (power), F9 IN4 (in), F10 Y1 (in), F11 I/O48 (io), F12 GOE0 (in), G1 I/O1 (io), G2 GOE1 (in), G3 TDI/IN0 (in), G4 ~{RESET} (in), G5 VCC (power), G6 GND (power), G7 GND (power), G8 VCC (power), G9 I/O47 (io), G10 IN5 (in), G11 Y2 (in), G12 TCK/IN7 (in), H1 I/O3 (io), H2 I/O2 (io), H3 I/O4 (io), H4 I/O0 (io), H5 GND (power), H6 VCC (power), H7 VCC (power), H8 GND (power), H9 I/O43 (io), H10 I/O46 (io), H11 I/O44 (io), H12 I/O45 (io), J1 I/O5 (io), J2 I/O8 (io), J3 I/O6 (io), J4 GND (power), J5 I/O17 (io), J6 TMS/IN1 (in), J7 IN3 (in), J8 I/O26 (io), J9 GND (power), J10 I/O42 (io), J11 I/O40 (io), J12 I/O41 (io), K1 I/O7 (io), K2 NC, K3 I/O12 (io), K4 I/O15 (io), K5 I/O19 (io), K6 I/O23 (io), K7 I/O25 (io), K8 I/O29 (io), K9 I/O32 (io), K10 I/O36 (io), K11 I/O37 (io), K12 I/O39 (io), L1 VCC (power), L2 I/O10 (io), L3 I/O11 (io), L4 I/O14 (io), L5 I/O20 (io), L6 I/O22 (io), L7 I/O24 (io), L8 I/O28 (io), L9 I/O31 (io), L10 I/O34 (io), L11 I/O38 (io), L12 VCC (power), M1 GND (power), M2 I/O9 (io), M3 I/O13 (io), M4 I/O16 (io), M5 I/O18 (io), M6 I/O21 (io), M7 IN2 (in), M8 I/O27 (io), M9 I/O30 (io), M10 I/O33 (io), M11 I/O35 (io), M12 GND (power)

## ispLSI2192VE-135LT128
designator U?
3.3V In-System Programmable SuperFAST High Density PLD
footprint TQFP128_N (Thin QFP, 128-Leads, Body 14x14mm, Pitch 0.4mm, IPC Medium Density)
footprint TQFP128_L (Thin QFP, 128-Leads, Body 14x14mm, Pitch 0.4mm, IPC High Density)
footprint TQFP128_M (Thin QFP, 128-Leads, Body 14x14mm, Pitch 0.4mm, IPC Low Density)
3D model 2192VE-TQFP128 (128-Pin Thin Quad Flat Pack 0.4 mm Pitch)
pins: 1 I/O85 (io), 2 VCC (power), 3 I/O86 (io), 4 I/O87 (io), 5 I/O88 (io), 6 I/O89 (io), 7 I/O90 (io), 8 I/O91 (io), 9 I/O92 (io), 10 I/O93 (io), 11 I/O94 (io), 12 I/O95 (io), 13 IN10 (in), 14 Y0 (in), 15 ~{RESE}T (in), 16 VCC (power), 17 GOE1 (in), 18 GND (power), 19 ~{BSCAN} (in), 20 TDI/IN0 (in), 21 I/O0 (io), 22 I/O1 (io), 23 I/O2 (io), 24 I/O3 (io), 25 I/O4 (io), 26 I/O5 (io), 27 I/O6 (io), 28 I/O7 (io), 29 I/O8 (io), 30 I/O9 (io), 31 VCC (power), 32 I/O10 (io), 33 I/O11 (io), 34 GND (power), 35 I/O12 (io), 36 I/O13 (io), 37 I/O14 (io), 38 I/O15 (io), 39 I/O16 (io), 40 I/O17 (io), 41 I/O18 (io), 42 I/O19 (io), 43 I/O20 (io), 44 I/O21 (io), 45 I/O22 (io), 46 I/O23 (io), 47 VCC (power), 48 TMS/IN1 (in), 49 IN3 (in), 50 GND (power), 51 I/O24 (io), 52 I/O25 (io), 53 I/O26 (io), 54 I/O27 (io), 55 I/O28 (io), 56 I/O29 (io), 57 I/O30 (io), 58 I/O31 (io), 59 I/O32 (io), 60 I/O33 (io), 61 I/O34 (io), 62 I/O35 (io), 63 GND (power), 64 I/O36 (io), 65 I/O37 (io), 66 VCC (power), 67 I/O38 (io), 68 I/O39 (io), 69 I/O40 (io), 70 I/O41 (io), 71 I/O42 (io), 72 I/O43 (io), 73 I/O44 (io), 74 I/O45 (io), 75 I/O46 (io), 76 I/O47 (io), 77 TCK/IN7 (in), 78 Y2 (in), 79 GND (power), 80 GOE0 (in), 81 VCC (power), 82 IN4 (in), 83 Y1 (in), 84 IN8 (in), 85 I/O48 (io), 86 I/O49 (io), 87 I/O50 (io), 88 I/O51 (io), 89 I/O52 (io), 90 I/O53 (io), 91 I/O54 (io), 92 I/O55 (io), 93 I/O56 (io), 94 I/O57 (io), 95 VCC (power), 96 I/O58 (io), 97 I/O59 (io), 98 GND (power), 99 I/O60 (io), 100 I/O61 (io), 101 I/O62 (io), 102 I/O63 (io), 103 I/O64 (io), 104 I/O65 (io), 105 I/O66 (io), 106 I/O67 (io), 107 I/O68 (io), 108 I/O69 (io), 109 I/O70 (io), 110 I/O71 (io), 111 GND (power), 112 TDO/IN6 (io), 113 IN9 (in), 114 VCC (power), 115 I/O72 (io), 116 I/O73 (io), 117 I/O74 (io), 118 I/O75 (io), 119 I/O76 (io), 120 I/O77 (io), 121 I/O78 (io), 122 I/O79 (io), 123 I/O80 (io), 124 I/O81 (io), 125 I/O82 (io), 126 I/O83 (io), 127 GND (power), 128 I/O84 (io)

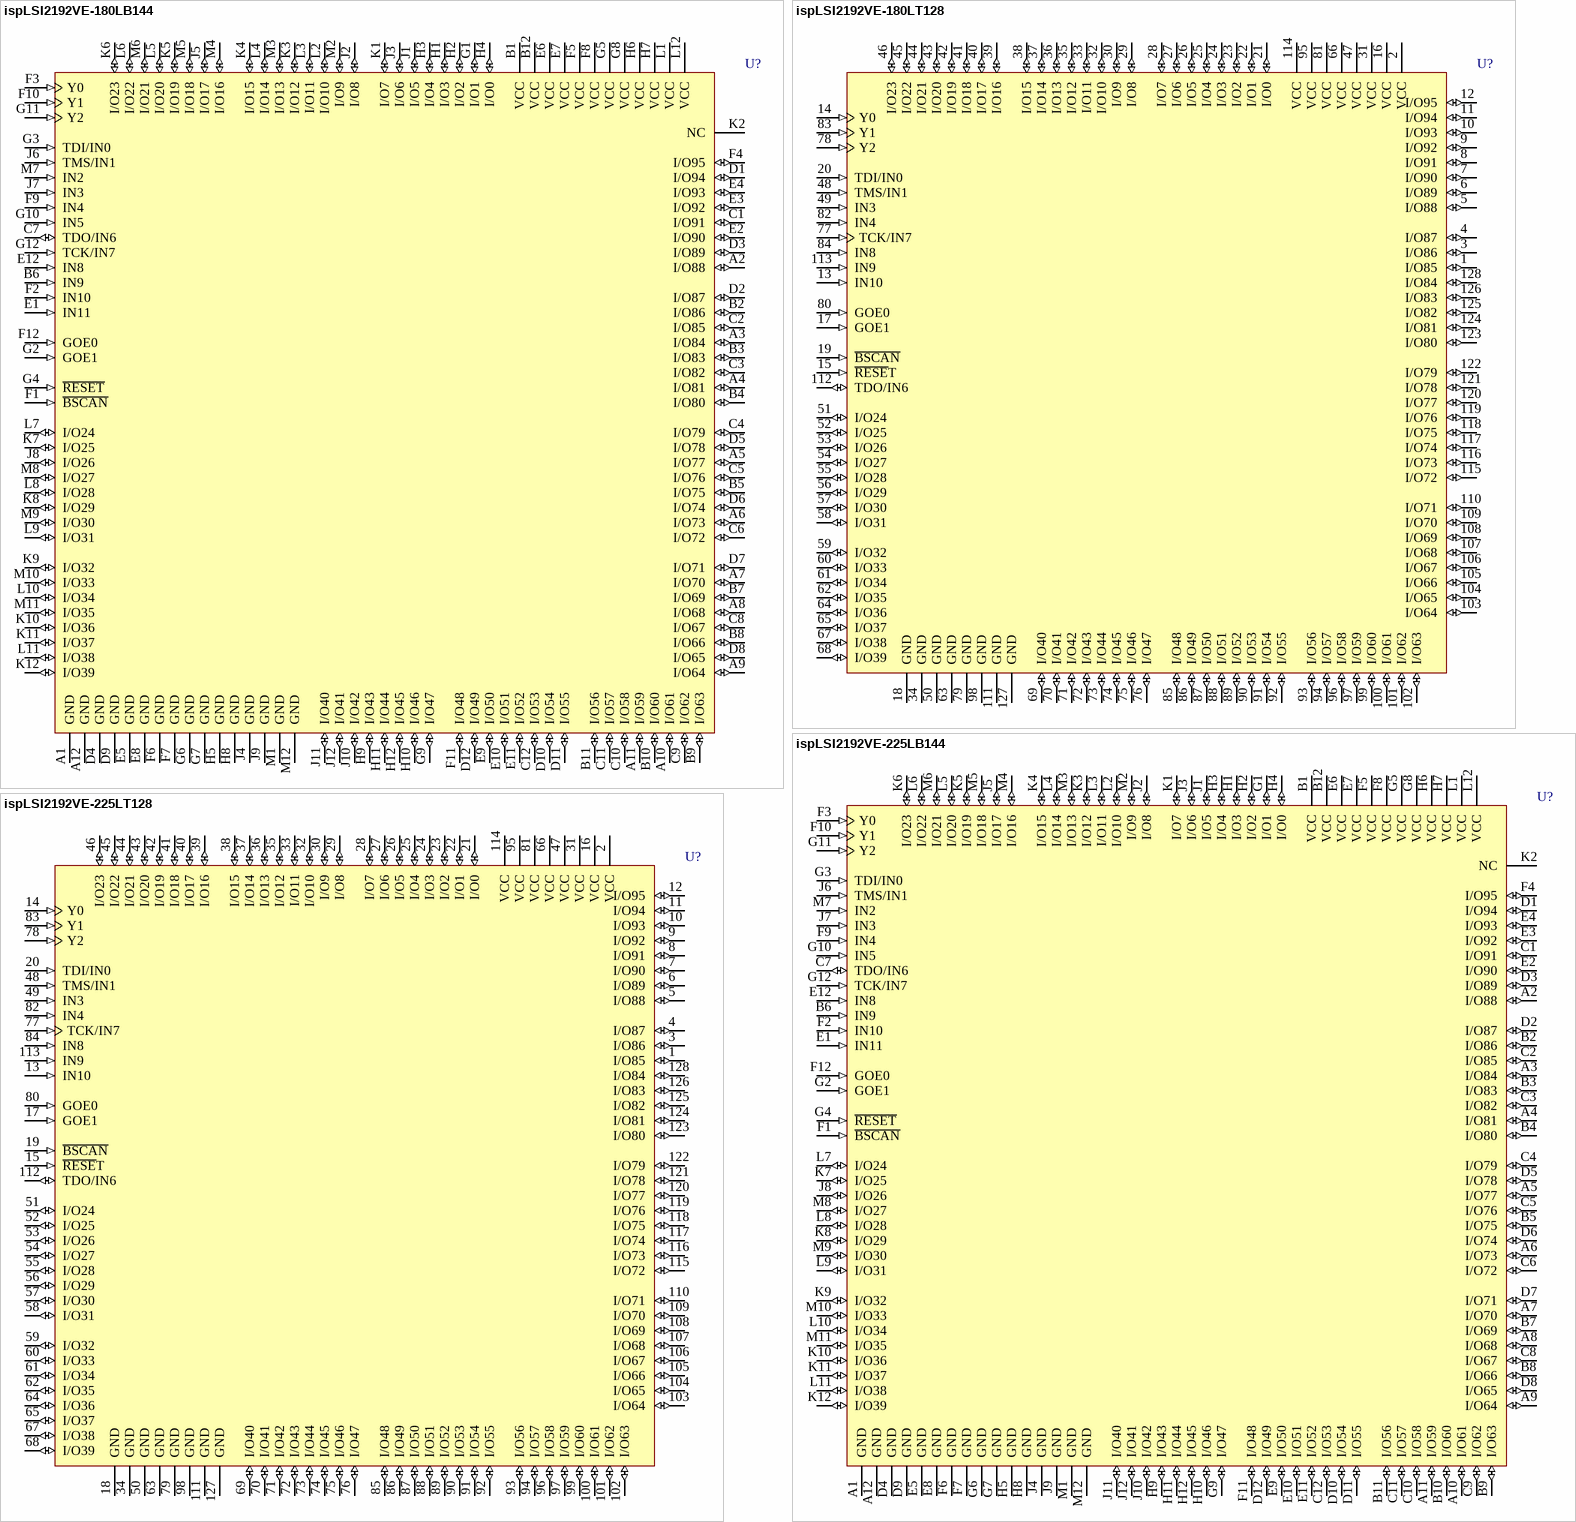
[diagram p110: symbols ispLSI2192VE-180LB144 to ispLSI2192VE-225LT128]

## ispLSI2192VE-180LB144
designator U?
3.3V In-System Programmable SuperFAST High Density PLD
footprint fpBGA144 (BGA, 144-Leads, Body 13x13mm, Pitch 1mm)
3D model 2192VE-fpBGA144 (144-Ball Fine Pitch Ball Grid Array (fpBGA144))
pins: A1 GND (power), A2 I/O88 (io), A3 I/O84 (io), A4 I/O81 (io), A5 I/O77 (io), A6 I/O73 (io), A7 I/O70 (io), A8 I/O68 (io), A9 I/O64 (io), A10 I/O61 (io), A11 I/O59 (io), A12 GND (power), B1 VCC (power), B2 I/O86 (io), B3 I/O83 (io), B4 I/O80 (io), B5 I/O75 (io), B6 IN9 (in), B7 I/O69 (io), B8 I/O66 (io), B9 I/O63 (io), B10 I/O60 (io), B11 I/O56 (io), B12 VCC (power), C1 I/O91 (io), C2 I/O85 (io), C3 I/O82 (io), C4 I/O79 (io), C5 I/O76 (io), C6 I/O72 (io), C7 TDO/IN6 (io), C8 I/O67 (io), C9 I/O62 (io), C10 I/O58 (io), C11 I/O57 (io), C12 I/O53 (io), D1 I/O94 (io), D2 I/O87 (io), D3 I/O89 (io), D4 GND (power), D5 I/O78 (io), D6 I/O74 (io), D7 I/O71 (io), D8 I/O65 (io), D9 GND (power), D10 I/O54 (io), D11 I/O55 (io), D12 I/O49 (io), E1 IN11 (in), E2 I/O90 (io), E3 I/O92 (io), E4 I/O93 (io), E5 GND (power), E6 VCC (power), E7 VCC (power), E8 GND (power), E9 I/O50 (io), E10 I/O51 (io), E11 I/O52 (io), E12 IN8 (in), F1 ~{BSCAN} (in), F2 IN10 (in), F3 Y0 (in), F4 I/O95 (io), F5 VCC (power), F6 GND (power), F7 GND (power), F8 VCC (power), F9 IN4 (in), F10 Y1 (in), F11 I/O48 (io), F12 GOE0 (in), G1 I/O1 (io), G2 GOE1 (in), G3 TDI/IN0 (in), G4 ~{RESET} (in), G5 VCC (power), G6 GND (power), G7 GND (power), G8 VCC (power), G9 I/O47 (io), G10 IN5 (in), G11 Y2 (in), G12 TCK/IN7 (in), H1 I/O3 (io), H2 I/O2 (io), H3 I/O4 (io), H4 I/O0 (io), H5 GND (power), H6 VCC (power), H7 VCC (power), H8 GND (power), H9 I/O43 (io), H10 I/O46 (io), H11 I/O44 (io), H12 I/O45 (io), J1 I/O5 (io), J2 I/O8 (io), J3 I/O6 (io), J4 GND (power), J5 I/O17 (io), J6 TMS/IN1 (in), J7 IN3 (in), J8 I/O26 (io), J9 GND (power), J10 I/O42 (io), J11 I/O40 (io), J12 I/O41 (io), K1 I/O7 (io), K2 NC, K3 I/O12 (io), K4 I/O15 (io), K5 I/O19 (io), K6 I/O23 (io), K7 I/O25 (io), K8 I/O29 (io), K9 I/O32 (io), K10 I/O36 (io), K11 I/O37 (io), K12 I/O39 (io), L1 VCC (power), L2 I/O10 (io), L3 I/O11 (io), L4 I/O14 (io), L5 I/O20 (io), L6 I/O22 (io), L7 I/O24 (io), L8 I/O28 (io), L9 I/O31 (io), L10 I/O34 (io), L11 I/O38 (io), L12 VCC (power), M1 GND (power), M2 I/O9 (io), M3 I/O13 (io), M4 I/O16 (io), M5 I/O18 (io), M6 I/O21 (io), M7 IN2 (in), M8 I/O27 (io), M9 I/O30 (io), M10 I/O33 (io), M11 I/O35 (io), M12 GND (power)

## ispLSI2192VE-180LT128
designator U?
3.3V In-System Programmable SuperFAST High Density PLD
footprint TQFP128_N (Thin QFP, 128-Leads, Body 14x14mm, Pitch 0.4mm, IPC Medium Density)
footprint TQFP128_L (Thin QFP, 128-Leads, Body 14x14mm, Pitch 0.4mm, IPC High Density)
footprint TQFP128_M (Thin QFP, 128-Leads, Body 14x14mm, Pitch 0.4mm, IPC Low Density)
3D model 2192VE-TQFP128 (128-Pin Thin Quad Flat Pack 0.4 mm Pitch)
pins: 1 I/O85 (io), 2 VCC (power), 3 I/O86 (io), 4 I/O87 (io), 5 I/O88 (io), 6 I/O89 (io), 7 I/O90 (io), 8 I/O91 (io), 9 I/O92 (io), 10 I/O93 (io), 11 I/O94 (io), 12 I/O95 (io), 13 IN10 (in), 14 Y0 (in), 15 ~{RESE}T (in), 16 VCC (power), 17 GOE1 (in), 18 GND (power), 19 ~{BSCAN} (in), 20 TDI/IN0 (in), 21 I/O0 (io), 22 I/O1 (io), 23 I/O2 (io), 24 I/O3 (io), 25 I/O4 (io), 26 I/O5 (io), 27 I/O6 (io), 28 I/O7 (io), 29 I/O8 (io), 30 I/O9 (io), 31 VCC (power), 32 I/O10 (io), 33 I/O11 (io), 34 GND (power), 35 I/O12 (io), 36 I/O13 (io), 37 I/O14 (io), 38 I/O15 (io), 39 I/O16 (io), 40 I/O17 (io), 41 I/O18 (io), 42 I/O19 (io), 43 I/O20 (io), 44 I/O21 (io), 45 I/O22 (io), 46 I/O23 (io), 47 VCC (power), 48 TMS/IN1 (in), 49 IN3 (in), 50 GND (power), 51 I/O24 (io), 52 I/O25 (io), 53 I/O26 (io), 54 I/O27 (io), 55 I/O28 (io), 56 I/O29 (io), 57 I/O30 (io), 58 I/O31 (io), 59 I/O32 (io), 60 I/O33 (io), 61 I/O34 (io), 62 I/O35 (io), 63 GND (power), 64 I/O36 (io), 65 I/O37 (io), 66 VCC (power), 67 I/O38 (io), 68 I/O39 (io), 69 I/O40 (io), 70 I/O41 (io), 71 I/O42 (io), 72 I/O43 (io), 73 I/O44 (io), 74 I/O45 (io), 75 I/O46 (io), 76 I/O47 (io), 77 TCK/IN7 (in), 78 Y2 (in), 79 GND (power), 80 GOE0 (in), 81 VCC (power), 82 IN4 (in), 83 Y1 (in), 84 IN8 (in), 85 I/O48 (io), 86 I/O49 (io), 87 I/O50 (io), 88 I/O51 (io), 89 I/O52 (io), 90 I/O53 (io), 91 I/O54 (io), 92 I/O55 (io), 93 I/O56 (io), 94 I/O57 (io), 95 VCC (power), 96 I/O58 (io), 97 I/O59 (io), 98 GND (power), 99 I/O60 (io), 100 I/O61 (io), 101 I/O62 (io), 102 I/O63 (io), 103 I/O64 (io), 104 I/O65 (io), 105 I/O66 (io), 106 I/O67 (io), 107 I/O68 (io), 108 I/O69 (io), 109 I/O70 (io), 110 I/O71 (io), 111 GND (power), 112 TDO/IN6 (io), 113 IN9 (in), 114 VCC (power), 115 I/O72 (io), 116 I/O73 (io), 117 I/O74 (io), 118 I/O75 (io), 119 I/O76 (io), 120 I/O77 (io), 121 I/O78 (io), 122 I/O79 (io), 123 I/O80 (io), 124 I/O81 (io), 125 I/O82 (io), 126 I/O83 (io), 127 GND (power), 128 I/O84 (io)

## ispLSI2192VE-225LB144
designator U?
3.3V In-System Programmable SuperFAST High Density PLD
footprint fpBGA144 (BGA, 144-Leads, Body 13x13mm, Pitch 1mm)
3D model 2192VE-fpBGA144 (144-Ball Fine Pitch Ball Grid Array (fpBGA144))
pins: A1 GND (power), A2 I/O88 (io), A3 I/O84 (io), A4 I/O81 (io), A5 I/O77 (io), A6 I/O73 (io), A7 I/O70 (io), A8 I/O68 (io), A9 I/O64 (io), A10 I/O61 (io), A11 I/O59 (io), A12 GND (power), B1 VCC (power), B2 I/O86 (io), B3 I/O83 (io), B4 I/O80 (io), B5 I/O75 (io), B6 IN9 (in), B7 I/O69 (io), B8 I/O66 (io), B9 I/O63 (io), B10 I/O60 (io), B11 I/O56 (io), B12 VCC (power), C1 I/O91 (io), C2 I/O85 (io), C3 I/O82 (io), C4 I/O79 (io), C5 I/O76 (io), C6 I/O72 (io), C7 TDO/IN6 (io), C8 I/O67 (io), C9 I/O62 (io), C10 I/O58 (io), C11 I/O57 (io), C12 I/O53 (io), D1 I/O94 (io), D2 I/O87 (io), D3 I/O89 (io), D4 GND (power), D5 I/O78 (io), D6 I/O74 (io), D7 I/O71 (io), D8 I/O65 (io), D9 GND (power), D10 I/O54 (io), D11 I/O55 (io), D12 I/O49 (io), E1 IN11 (in), E2 I/O90 (io), E3 I/O92 (io), E4 I/O93 (io), E5 GND (power), E6 VCC (power), E7 VCC (power), E8 GND (power), E9 I/O50 (io), E10 I/O51 (io), E11 I/O52 (io), E12 IN8 (in), F1 ~{BSCAN} (in), F2 IN10 (in), F3 Y0 (in), F4 I/O95 (io), F5 VCC (power), F6 GND (power), F7 GND (power), F8 VCC (power), F9 IN4 (in), F10 Y1 (in), F11 I/O48 (io), F12 GOE0 (in), G1 I/O1 (io), G2 GOE1 (in), G3 TDI/IN0 (in), G4 ~{RESET} (in), G5 VCC (power), G6 GND (power), G7 GND (power), G8 VCC (power), G9 I/O47 (io), G10 IN5 (in), G11 Y2 (in), G12 TCK/IN7 (in), H1 I/O3 (io), H2 I/O2 (io), H3 I/O4 (io), H4 I/O0 (io), H5 GND (power), H6 VCC (power), H7 VCC (power), H8 GND (power), H9 I/O43 (io), H10 I/O46 (io), H11 I/O44 (io), H12 I/O45 (io), J1 I/O5 (io), J2 I/O8 (io), J3 I/O6 (io), J4 GND (power), J5 I/O17 (io), J6 TMS/IN1 (in), J7 IN3 (in), J8 I/O26 (io), J9 GND (power), J10 I/O42 (io), J11 I/O40 (io), J12 I/O41 (io), K1 I/O7 (io), K2 NC, K3 I/O12 (io), K4 I/O15 (io), K5 I/O19 (io), K6 I/O23 (io), K7 I/O25 (io), K8 I/O29 (io), K9 I/O32 (io), K10 I/O36 (io), K11 I/O37 (io), K12 I/O39 (io), L1 VCC (power), L2 I/O10 (io), L3 I/O11 (io), L4 I/O14 (io), L5 I/O20 (io), L6 I/O22 (io), L7 I/O24 (io), L8 I/O28 (io), L9 I/O31 (io), L10 I/O34 (io), L11 I/O38 (io), L12 VCC (power), M1 GND (power), M2 I/O9 (io), M3 I/O13 (io), M4 I/O16 (io), M5 I/O18 (io), M6 I/O21 (io), M7 IN2 (in), M8 I/O27 (io), M9 I/O30 (io), M10 I/O33 (io), M11 I/O35 (io), M12 GND (power)

## ispLSI2192VE-225LT128
designator U?
3.3V In-System Programmable SuperFAST High Density PLD
footprint TQFP128_N (Thin QFP, 128-Leads, Body 14x14mm, Pitch 0.4mm, IPC Medium Density)
footprint TQFP128_L (Thin QFP, 128-Leads, Body 14x14mm, Pitch 0.4mm, IPC High Density)
footprint TQFP128_M (Thin QFP, 128-Leads, Body 14x14mm, Pitch 0.4mm, IPC Low Density)
3D model 2192VE-TQFP128 (128-Pin Thin Quad Flat Pack 0.4 mm Pitch)
pins: 1 I/O85 (io), 2 VCC (power), 3 I/O86 (io), 4 I/O87 (io), 5 I/O88 (io), 6 I/O89 (io), 7 I/O90 (io), 8 I/O91 (io), 9 I/O92 (io), 10 I/O93 (io), 11 I/O94 (io), 12 I/O95 (io), 13 IN10 (in), 14 Y0 (in), 15 ~{RESE}T (in), 16 VCC (power), 17 GOE1 (in), 18 GND (power), 19 ~{BSCAN} (in), 20 TDI/IN0 (in), 21 I/O0 (io), 22 I/O1 (io), 23 I/O2 (io), 24 I/O3 (io), 25 I/O4 (io), 26 I/O5 (io), 27 I/O6 (io), 28 I/O7 (io), 29 I/O8 (io), 30 I/O9 (io), 31 VCC (power), 32 I/O10 (io), 33 I/O11 (io), 34 GND (power), 35 I/O12 (io), 36 I/O13 (io), 37 I/O14 (io), 38 I/O15 (io), 39 I/O16 (io), 40 I/O17 (io), 41 I/O18 (io), 42 I/O19 (io), 43 I/O20 (io), 44 I/O21 (io), 45 I/O22 (io), 46 I/O23 (io), 47 VCC (power), 48 TMS/IN1 (in), 49 IN3 (in), 50 GND (power), 51 I/O24 (io), 52 I/O25 (io), 53 I/O26 (io), 54 I/O27 (io), 55 I/O28 (io), 56 I/O29 (io), 57 I/O30 (io), 58 I/O31 (io), 59 I/O32 (io), 60 I/O33 (io), 61 I/O34 (io), 62 I/O35 (io), 63 GND (power), 64 I/O36 (io), 65 I/O37 (io), 66 VCC (power), 67 I/O38 (io), 68 I/O39 (io), 69 I/O40 (io), 70 I/O41 (io), 71 I/O42 (io), 72 I/O43 (io), 73 I/O44 (io), 74 I/O45 (io), 75 I/O46 (io), 76 I/O47 (io), 77 TCK/IN7 (in), 78 Y2 (in), 79 GND (power), 80 GOE0 (in), 81 VCC (power), 82 IN4 (in), 83 Y1 (in), 84 IN8 (in), 85 I/O48 (io), 86 I/O49 (io), 87 I/O50 (io), 88 I/O51 (io), 89 I/O52 (io), 90 I/O53 (io), 91 I/O54 (io), 92 I/O55 (io), 93 I/O56 (io), 94 I/O57 (io), 95 VCC (power), 96 I/O58 (io), 97 I/O59 (io), 98 GND (power), 99 I/O60 (io), 100 I/O61 (io), 101 I/O62 (io), 102 I/O63 (io), 103 I/O64 (io), 104 I/O65 (io), 105 I/O66 (io), 106 I/O67 (io), 107 I/O68 (io), 108 I/O69 (io), 109 I/O70 (io), 110 I/O71 (io), 111 GND (power), 112 TDO/IN6 (io), 113 IN9 (in), 114 VCC (power), 115 I/O72 (io), 116 I/O73 (io), 117 I/O74 (io), 118 I/O75 (io), 119 I/O76 (io), 120 I/O77 (io), 121 I/O78 (io), 122 I/O79 (io), 123 I/O80 (io), 124 I/O81 (io), 125 I/O82 (io), 126 I/O83 (io), 127 GND (power), 128 I/O84 (io)

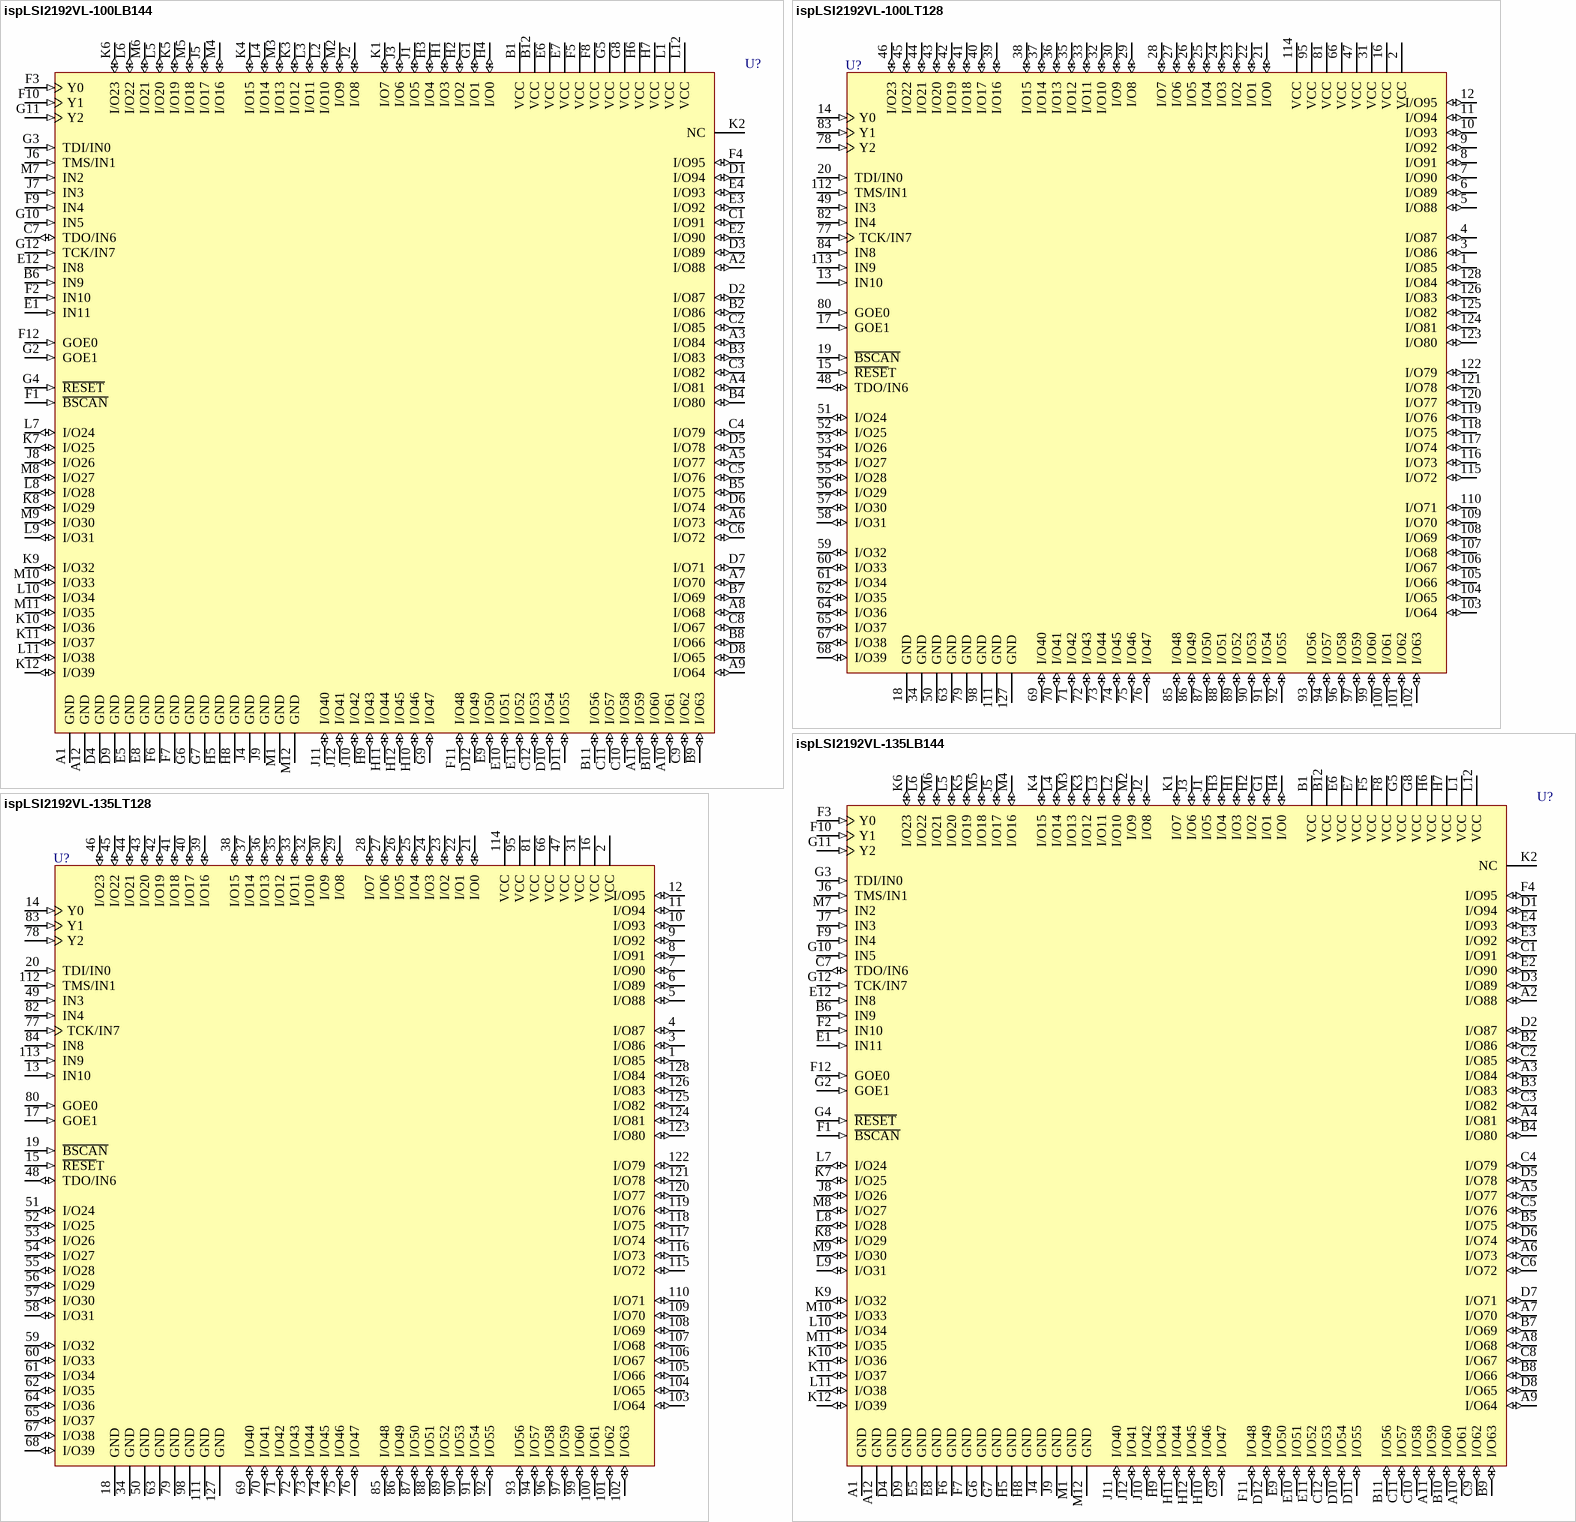
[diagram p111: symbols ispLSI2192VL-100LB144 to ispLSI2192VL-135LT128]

## ispLSI2192VL-100LB144
designator U?
2.5V In-System Programmable SuperFAST High Density PLD
footprint fpBGA144 (BGA, 144-Leads, Body 13x13mm, Pitch 1mm)
3D model 2192VL-fpBGA144 (144-Ball Fine Pitch Ball Grid Array (fpBGA144))
pins: A1 GND (power), A2 I/O88 (io), A3 I/O84 (io), A4 I/O81 (io), A5 I/O77 (io), A6 I/O73 (io), A7 I/O70 (io), A8 I/O68 (io), A9 I/O64 (io), A10 I/O61 (io), A11 I/O59 (io), A12 GND (power), B1 VCC (power), B2 I/O86 (io), B3 I/O83 (io), B4 I/O80 (io), B5 I/O75 (io), B6 IN9 (in), B7 I/O69 (io), B8 I/O66 (io), B9 I/O63 (io), B10 I/O60 (io), B11 I/O56 (io), B12 VCC (power), C1 I/O91 (io), C2 I/O85 (io), C3 I/O82 (io), C4 I/O79 (io), C5 I/O76 (io), C6 I/O72 (io), C7 TDO/IN6 (io), C8 I/O67 (io), C9 I/O62 (io), C10 I/O58 (io), C11 I/O57 (io), C12 I/O53 (io), D1 I/O94 (io), D2 I/O87 (io), D3 I/O89 (io), D4 GND (power), D5 I/O78 (io), D6 I/O74 (io), D7 I/O71 (io), D8 I/O65 (io), D9 GND (power), D10 I/O54 (io), D11 I/O55 (io), D12 I/O49 (io), E1 IN11 (in), E2 I/O90 (io), E3 I/O92 (io), E4 I/O93 (io), E5 GND (power), E6 VCC (power), E7 VCC (power), E8 GND (power), E9 I/O50 (io), E10 I/O51 (io), E11 I/O52 (io), E12 IN8 (in), F1 ~{BSCAN} (in), F2 IN10 (in), F3 Y0 (in), F4 I/O95 (io), F5 VCC (power), F6 GND (power), F7 GND (power), F8 VCC (power), F9 IN4 (in), F10 Y1 (in), F11 I/O48 (io), F12 GOE0 (in), G1 I/O1 (io), G2 GOE1 (in), G3 TDI/IN0 (in), G4 ~{RESET} (in), G5 VCC (power), G6 GND (power), G7 GND (power), G8 VCC (power), G9 I/O47 (io), G10 IN5 (in), G11 Y2 (in), G12 TCK/IN7 (in), H1 I/O3 (io), H2 I/O2 (io), H3 I/O4 (io), H4 I/O0 (io), H5 GND (power), H6 VCC (power), H7 VCC (power), H8 GND (power), H9 I/O43 (io), H10 I/O46 (io), H11 I/O44 (io), H12 I/O45 (io), J1 I/O5 (io), J2 I/O8 (io), J3 I/O6 (io), J4 GND (power), J5 I/O17 (io), J6 TMS/IN1 (in), J7 IN3 (in), J8 I/O26 (io), J9 GND (power), J10 I/O42 (io), J11 I/O40 (io), J12 I/O41 (io), K1 I/O7 (io), K2 NC, K3 I/O12 (io), K4 I/O15 (io), K5 I/O19 (io), K6 I/O23 (io), K7 I/O25 (io), K8 I/O29 (io), K9 I/O32 (io), K10 I/O36 (io), K11 I/O37 (io), K12 I/O39 (io), L1 VCC (power), L2 I/O10 (io), L3 I/O11 (io), L4 I/O14 (io), L5 I/O20 (io), L6 I/O22 (io), L7 I/O24 (io), L8 I/O28 (io), L9 I/O31 (io), L10 I/O34 (io), L11 I/O38 (io), L12 VCC (power), M1 GND (power), M2 I/O9 (io), M3 I/O13 (io), M4 I/O16 (io), M5 I/O18 (io), M6 I/O21 (io), M7 IN2 (in), M8 I/O27 (io), M9 I/O30 (io), M10 I/O33 (io), M11 I/O35 (io), M12 GND (power)

## ispLSI2192VL-100LT128
designator U?
2.5V In-System Programmable SuperFAST High Density PLD
footprint TQFP128_N (Thin QFP, 128-Leads, Body 14x14mm, Pitch 0.4mm, IPC Medium Density)
footprint TQFP128_L (Thin QFP, 128-Leads, Body 14x14mm, Pitch 0.4mm, IPC High Density)
footprint TQFP128_M (Thin QFP, 128-Leads, Body 14x14mm, Pitch 0.4mm, IPC Low Density)
3D model 2192VL-TQFP128 (128-Pin Thin Quad Flat Pack 0.4 mm Pitch)
pins: 1 I/O85 (io), 2 VCC (power), 3 I/O86 (io), 4 I/O87 (io), 5 I/O88 (io), 6 I/O89 (io), 7 I/O90 (io), 8 I/O91 (io), 9 I/O92 (io), 10 I/O93 (io), 11 I/O94 (io), 12 I/O95 (io), 13 IN10 (in), 14 Y0 (in), 15 ~{RESE}T (in), 16 VCC (power), 17 GOE1 (in), 18 GND (power), 19 ~{BSCAN} (in), 20 TDI/IN0 (in), 21 I/O0 (io), 22 I/O1 (io), 23 I/O2 (io), 24 I/O3 (io), 25 I/O4 (io), 26 I/O5 (io), 27 I/O6 (io), 28 I/O7 (io), 29 I/O8 (io), 30 I/O9 (io), 31 VCC (power), 32 I/O10 (io), 33 I/O11 (io), 34 GND (power), 35 I/O12 (io), 36 I/O13 (io), 37 I/O14 (io), 38 I/O15 (io), 39 I/O16 (io), 40 I/O17 (io), 41 I/O18 (io), 42 I/O19 (io), 43 I/O20 (io), 44 I/O21 (io), 45 I/O22 (io), 46 I/O23 (io), 47 VCC (power), 48 TDO/IN6 (io), 49 IN3 (in), 50 GND (power), 51 I/O24 (io), 52 I/O25 (io), 53 I/O26 (io), 54 I/O27 (io), 55 I/O28 (io), 56 I/O29 (io), 57 I/O30 (io), 58 I/O31 (io), 59 I/O32 (io), 60 I/O33 (io), 61 I/O34 (io), 62 I/O35 (io), 63 GND (power), 64 I/O36 (io), 65 I/O37 (io), 66 VCC (power), 67 I/O38 (io), 68 I/O39 (io), 69 I/O40 (io), 70 I/O41 (io), 71 I/O42 (io), 72 I/O43 (io), 73 I/O44 (io), 74 I/O45 (io), 75 I/O46 (io), 76 I/O47 (io), 77 TCK/IN7 (in), 78 Y2 (in), 79 GND (power), 80 GOE0 (in), 81 VCC (power), 82 IN4 (in), 83 Y1 (in), 84 IN8 (in), 85 I/O48 (io), 86 I/O49 (io), 87 I/O50 (io), 88 I/O51 (io), 89 I/O52 (io), 90 I/O53 (io), 91 I/O54 (io), 92 I/O55 (io), 93 I/O56 (io), 94 I/O57 (io), 95 VCC (power), 96 I/O58 (io), 97 I/O59 (io), 98 GND (power), 99 I/O60 (io), 100 I/O61 (io), 101 I/O62 (io), 102 I/O63 (io), 103 I/O64 (io), 104 I/O65 (io), 105 I/O66 (io), 106 I/O67 (io), 107 I/O68 (io), 108 I/O69 (io), 109 I/O70 (io), 110 I/O71 (io), 111 GND (power), 112 TMS/IN1 (in), 113 IN9 (in), 114 VCC (power), 115 I/O72 (io), 116 I/O73 (io), 117 I/O74 (io), 118 I/O75 (io), 119 I/O76 (io), 120 I/O77 (io), 121 I/O78 (io), 122 I/O79 (io), 123 I/O80 (io), 124 I/O81 (io), 125 I/O82 (io), 126 I/O83 (io), 127 GND (power), 128 I/O84 (io)

## ispLSI2192VL-135LB144
designator U?
2.5V In-System Programmable SuperFAST High Density PLD
footprint fpBGA144 (BGA, 144-Leads, Body 13x13mm, Pitch 1mm)
3D model 2192VL-fpBGA144 (144-Ball Fine Pitch Ball Grid Array (fpBGA144))
pins: A1 GND (power), A2 I/O88 (io), A3 I/O84 (io), A4 I/O81 (io), A5 I/O77 (io), A6 I/O73 (io), A7 I/O70 (io), A8 I/O68 (io), A9 I/O64 (io), A10 I/O61 (io), A11 I/O59 (io), A12 GND (power), B1 VCC (power), B2 I/O86 (io), B3 I/O83 (io), B4 I/O80 (io), B5 I/O75 (io), B6 IN9 (in), B7 I/O69 (io), B8 I/O66 (io), B9 I/O63 (io), B10 I/O60 (io), B11 I/O56 (io), B12 VCC (power), C1 I/O91 (io), C2 I/O85 (io), C3 I/O82 (io), C4 I/O79 (io), C5 I/O76 (io), C6 I/O72 (io), C7 TDO/IN6 (io), C8 I/O67 (io), C9 I/O62 (io), C10 I/O58 (io), C11 I/O57 (io), C12 I/O53 (io), D1 I/O94 (io), D2 I/O87 (io), D3 I/O89 (io), D4 GND (power), D5 I/O78 (io), D6 I/O74 (io), D7 I/O71 (io), D8 I/O65 (io), D9 GND (power), D10 I/O54 (io), D11 I/O55 (io), D12 I/O49 (io), E1 IN11 (in), E2 I/O90 (io), E3 I/O92 (io), E4 I/O93 (io), E5 GND (power), E6 VCC (power), E7 VCC (power), E8 GND (power), E9 I/O50 (io), E10 I/O51 (io), E11 I/O52 (io), E12 IN8 (in), F1 ~{BSCAN} (in), F2 IN10 (in), F3 Y0 (in), F4 I/O95 (io), F5 VCC (power), F6 GND (power), F7 GND (power), F8 VCC (power), F9 IN4 (in), F10 Y1 (in), F11 I/O48 (io), F12 GOE0 (in), G1 I/O1 (io), G2 GOE1 (in), G3 TDI/IN0 (in), G4 ~{RESET} (in), G5 VCC (power), G6 GND (power), G7 GND (power), G8 VCC (power), G9 I/O47 (io), G10 IN5 (in), G11 Y2 (in), G12 TCK/IN7 (in), H1 I/O3 (io), H2 I/O2 (io), H3 I/O4 (io), H4 I/O0 (io), H5 GND (power), H6 VCC (power), H7 VCC (power), H8 GND (power), H9 I/O43 (io), H10 I/O46 (io), H11 I/O44 (io), H12 I/O45 (io), J1 I/O5 (io), J2 I/O8 (io), J3 I/O6 (io), J4 GND (power), J5 I/O17 (io), J6 TMS/IN1 (in), J7 IN3 (in), J8 I/O26 (io), J9 GND (power), J10 I/O42 (io), J11 I/O40 (io), J12 I/O41 (io), K1 I/O7 (io), K2 NC, K3 I/O12 (io), K4 I/O15 (io), K5 I/O19 (io), K6 I/O23 (io), K7 I/O25 (io), K8 I/O29 (io), K9 I/O32 (io), K10 I/O36 (io), K11 I/O37 (io), K12 I/O39 (io), L1 VCC (power), L2 I/O10 (io), L3 I/O11 (io), L4 I/O14 (io), L5 I/O20 (io), L6 I/O22 (io), L7 I/O24 (io), L8 I/O28 (io), L9 I/O31 (io), L10 I/O34 (io), L11 I/O38 (io), L12 VCC (power), M1 GND (power), M2 I/O9 (io), M3 I/O13 (io), M4 I/O16 (io), M5 I/O18 (io), M6 I/O21 (io), M7 IN2 (in), M8 I/O27 (io), M9 I/O30 (io), M10 I/O33 (io), M11 I/O35 (io), M12 GND (power)

## ispLSI2192VL-135LT128
designator U?
2.5V In-System Programmable SuperFAST High Density PLD
footprint TQFP128_N (Thin QFP, 128-Leads, Body 14x14mm, Pitch 0.4mm, IPC Medium Density)
footprint TQFP128_L (Thin QFP, 128-Leads, Body 14x14mm, Pitch 0.4mm, IPC High Density)
footprint TQFP128_M (Thin QFP, 128-Leads, Body 14x14mm, Pitch 0.4mm, IPC Low Density)
3D model 2192VL-TQFP128 (128-Pin Thin Quad Flat Pack 0.4 mm Pitch)
pins: 1 I/O85 (io), 2 VCC (power), 3 I/O86 (io), 4 I/O87 (io), 5 I/O88 (io), 6 I/O89 (io), 7 I/O90 (io), 8 I/O91 (io), 9 I/O92 (io), 10 I/O93 (io), 11 I/O94 (io), 12 I/O95 (io), 13 IN10 (in), 14 Y0 (in), 15 ~{RESE}T (in), 16 VCC (power), 17 GOE1 (in), 18 GND (power), 19 ~{BSCAN} (in), 20 TDI/IN0 (in), 21 I/O0 (io), 22 I/O1 (io), 23 I/O2 (io), 24 I/O3 (io), 25 I/O4 (io), 26 I/O5 (io), 27 I/O6 (io), 28 I/O7 (io), 29 I/O8 (io), 30 I/O9 (io), 31 VCC (power), 32 I/O10 (io), 33 I/O11 (io), 34 GND (power), 35 I/O12 (io), 36 I/O13 (io), 37 I/O14 (io), 38 I/O15 (io), 39 I/O16 (io), 40 I/O17 (io), 41 I/O18 (io), 42 I/O19 (io), 43 I/O20 (io), 44 I/O21 (io), 45 I/O22 (io), 46 I/O23 (io), 47 VCC (power), 48 TDO/IN6 (io), 49 IN3 (in), 50 GND (power), 51 I/O24 (io), 52 I/O25 (io), 53 I/O26 (io), 54 I/O27 (io), 55 I/O28 (io), 56 I/O29 (io), 57 I/O30 (io), 58 I/O31 (io), 59 I/O32 (io), 60 I/O33 (io), 61 I/O34 (io), 62 I/O35 (io), 63 GND (power), 64 I/O36 (io), 65 I/O37 (io), 66 VCC (power), 67 I/O38 (io), 68 I/O39 (io), 69 I/O40 (io), 70 I/O41 (io), 71 I/O42 (io), 72 I/O43 (io), 73 I/O44 (io), 74 I/O45 (io), 75 I/O46 (io), 76 I/O47 (io), 77 TCK/IN7 (in), 78 Y2 (in), 79 GND (power), 80 GOE0 (in), 81 VCC (power), 82 IN4 (in), 83 Y1 (in), 84 IN8 (in), 85 I/O48 (io), 86 I/O49 (io), 87 I/O50 (io), 88 I/O51 (io), 89 I/O52 (io), 90 I/O53 (io), 91 I/O54 (io), 92 I/O55 (io), 93 I/O56 (io), 94 I/O57 (io), 95 VCC (power), 96 I/O58 (io), 97 I/O59 (io), 98 GND (power), 99 I/O60 (io), 100 I/O61 (io), 101 I/O62 (io), 102 I/O63 (io), 103 I/O64 (io), 104 I/O65 (io), 105 I/O66 (io), 106 I/O67 (io), 107 I/O68 (io), 108 I/O69 (io), 109 I/O70 (io), 110 I/O71 (io), 111 GND (power), 112 TMS/IN1 (in), 113 IN9 (in), 114 VCC (power), 115 I/O72 (io), 116 I/O73 (io), 117 I/O74 (io), 118 I/O75 (io), 119 I/O76 (io), 120 I/O77 (io), 121 I/O78 (io), 122 I/O79 (io), 123 I/O80 (io), 124 I/O81 (io), 125 I/O82 (io), 126 I/O83 (io), 127 GND (power), 128 I/O84 (io)

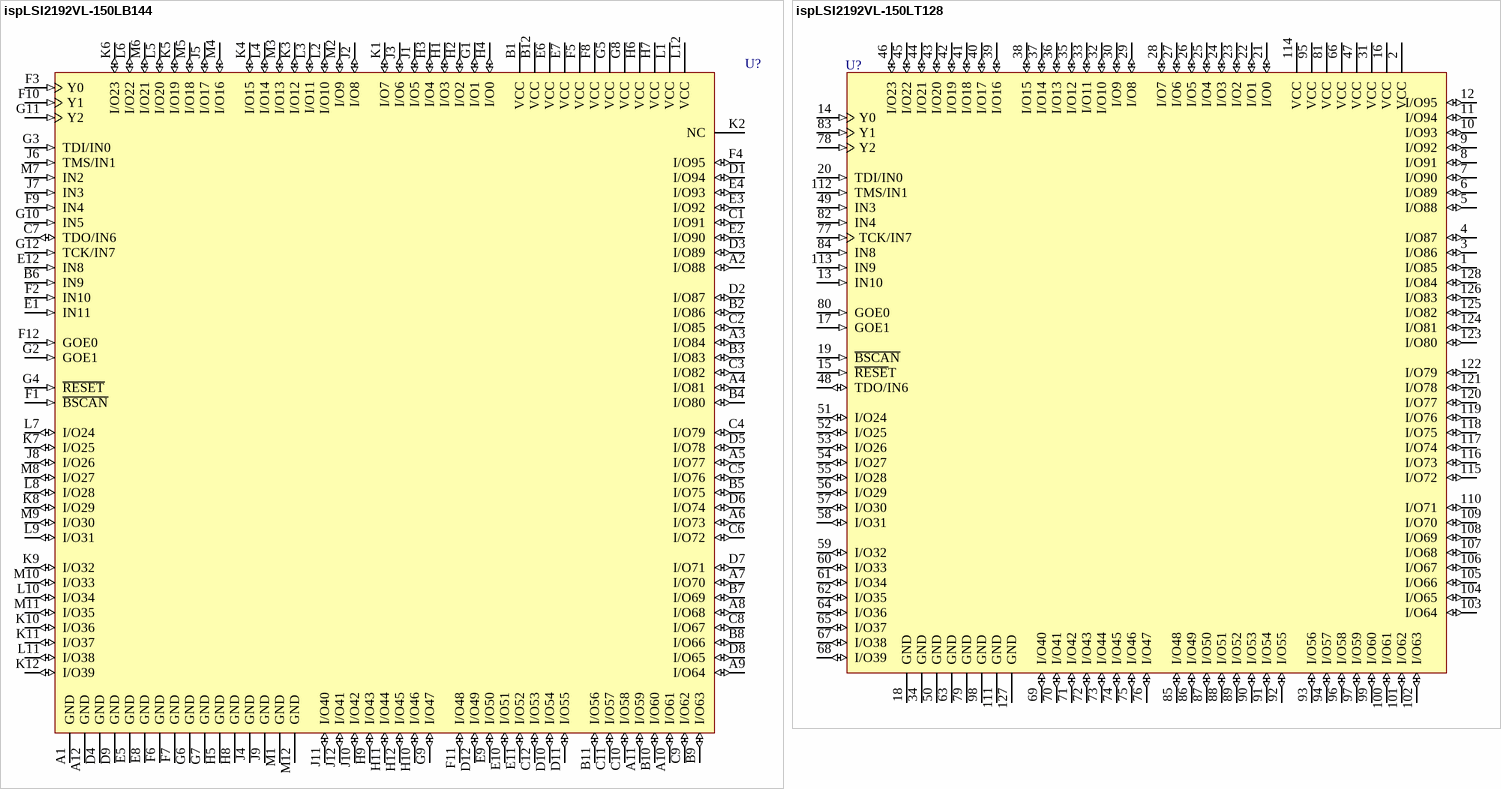
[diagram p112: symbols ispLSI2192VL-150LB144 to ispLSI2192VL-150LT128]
